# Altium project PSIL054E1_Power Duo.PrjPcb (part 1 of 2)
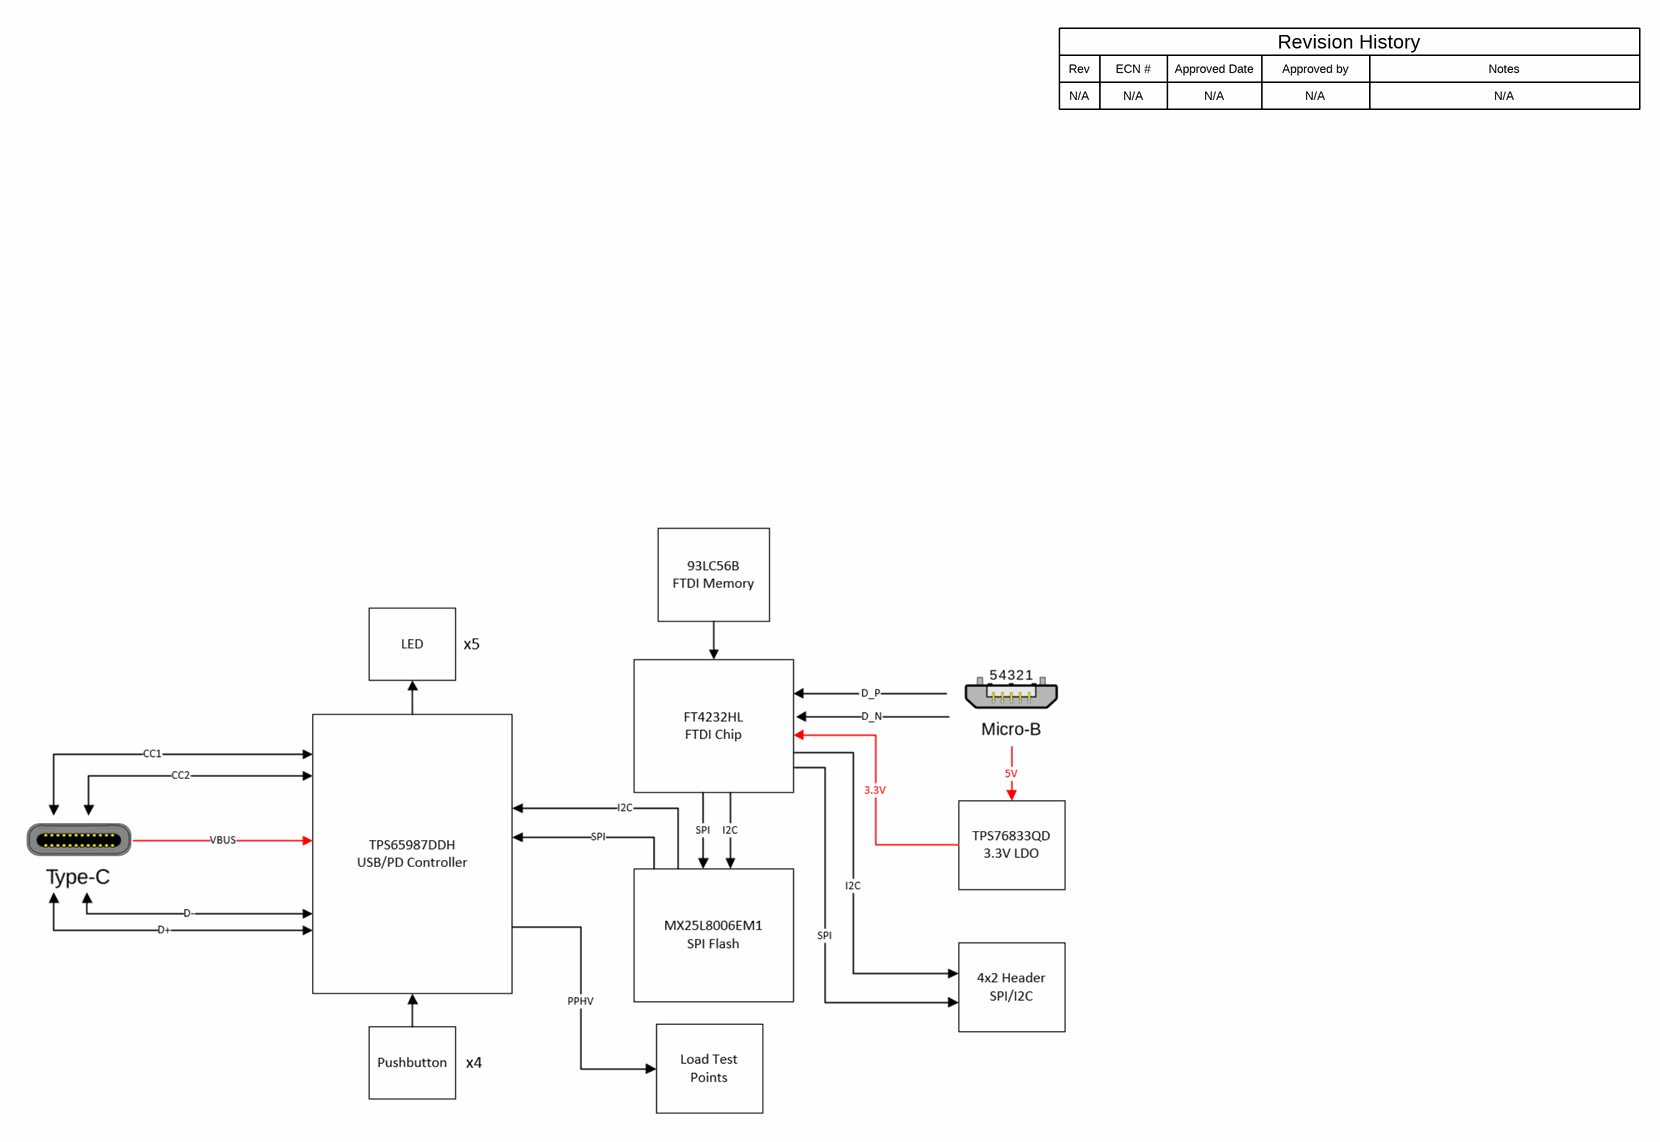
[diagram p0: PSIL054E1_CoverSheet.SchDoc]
CopyrightYear: 2018; PCB_Layout: Eric Beljaars/Adam McGaffin; PCB_Rev: E1; PRJ_Customer: Public Release; PRJ_Engineer: Eric Beljaars/Adam McGaffin; PRJ_Number: PSIL054; PRJ_Title: Power Duo; SCH_Rev: E1; TechSupport: http://www.ti.com/support; TID: TIDA-050014
9 sheets, 248 parts. Net scope: flat (ports and power ports of the same name join across sheets).
Board file: PSIL054E1_PCB.PcbDoc
Sheets:
  PSIL054E1_CoverSheet.SchDoc
  PSIL054E1_Variable DCDC.SchDoc
  PSIL054E1_Source PD Controller.SchDoc
  PSIL054E1_Bypass Power Path.SchDoc
  PSIL054E1_Source Type-C Connector.SchDoc
  PSIL054E1_Sink PD Controller.SchDoc
  PSIL054E1_FTDI.SchDoc
  PSIL054E1_Sink Buttons LEDs.SchDoc
  PSIL054E1_EVM_Hardware.SchDoc

## Sheet PSIL054E1_CoverSheet.SchDoc
size 431 x 279 mm; Date: Not shown in title block; ApprovedBy: Not shown in title block; CheckedBy: Not shown in title block; Author: Not shown in title block; CompanyName: Not shown in title block; Engineer: Not shown in title block; Organization: Not shown in title block; Address1: Not shown in title block; Address2: Not shown in title block; Address3: Not shown in title block; Address4: Not shown in title block; DocumentNumber: 1; Revision: Use project parameter SCH_Rev; SheetNumber: 1; SheetTotal: 9; PageSetup: Record=PageOptions¦CenterHorizontal=True¦CenterVertical=True¦PrintScale=1.00¦XCorrection=1.00¦YCorrection=1.00¦PrintKind=0¦BorderSize=5000000¦LeftOffset=0¦BottomOffset=0¦Orientation=2¦PaperLength=1000¦PaperWidth=1000¦Scale=100¦PaperSource=15¦PrintQuality=600¦MediaType=1¦DitherType=10¦PaperKind=Letter¦PrintScaleMode=1

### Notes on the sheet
- Rev
- N/A
- ECN #
- Approved Date
- Approved by
- Revision History
- Notes

## Sheet PSIL054E1_Variable DCDC.SchDoc
size 431 x 279 mm; Date: Not shown in title block; ApprovedBy: Not shown in title block; CheckedBy: Not shown in title block; Author: Not shown in title block; CompanyName: Not shown in title block; Engineer: Not shown in title block; Organization: Not shown in title block; Address1: Not shown in title block; Address2: Not shown in title block; Address3: Not shown in title block; Address4: Not shown in title block; DocumentNumber: 1; Revision: Use project parameter SCH_Rev; SheetNumber: 2; SheetTotal: 9; PageSetup: Record=PageOptions¦CenterHorizontal=True¦CenterVertical=True¦PrintScale=1.00¦XCorrection=1.00¦YCorrection=1.00¦PrintKind=0¦BorderSize=5000000¦LeftOffset=0¦BottomOffset=0¦Orientation=2¦PaperLength=1000¦PaperWidth=1000¦Scale=100¦PaperSource=15¦PrintQuality=600¦MediaType=1¦DitherType=10¦PaperKind=Letter¦PrintScaleMode=1
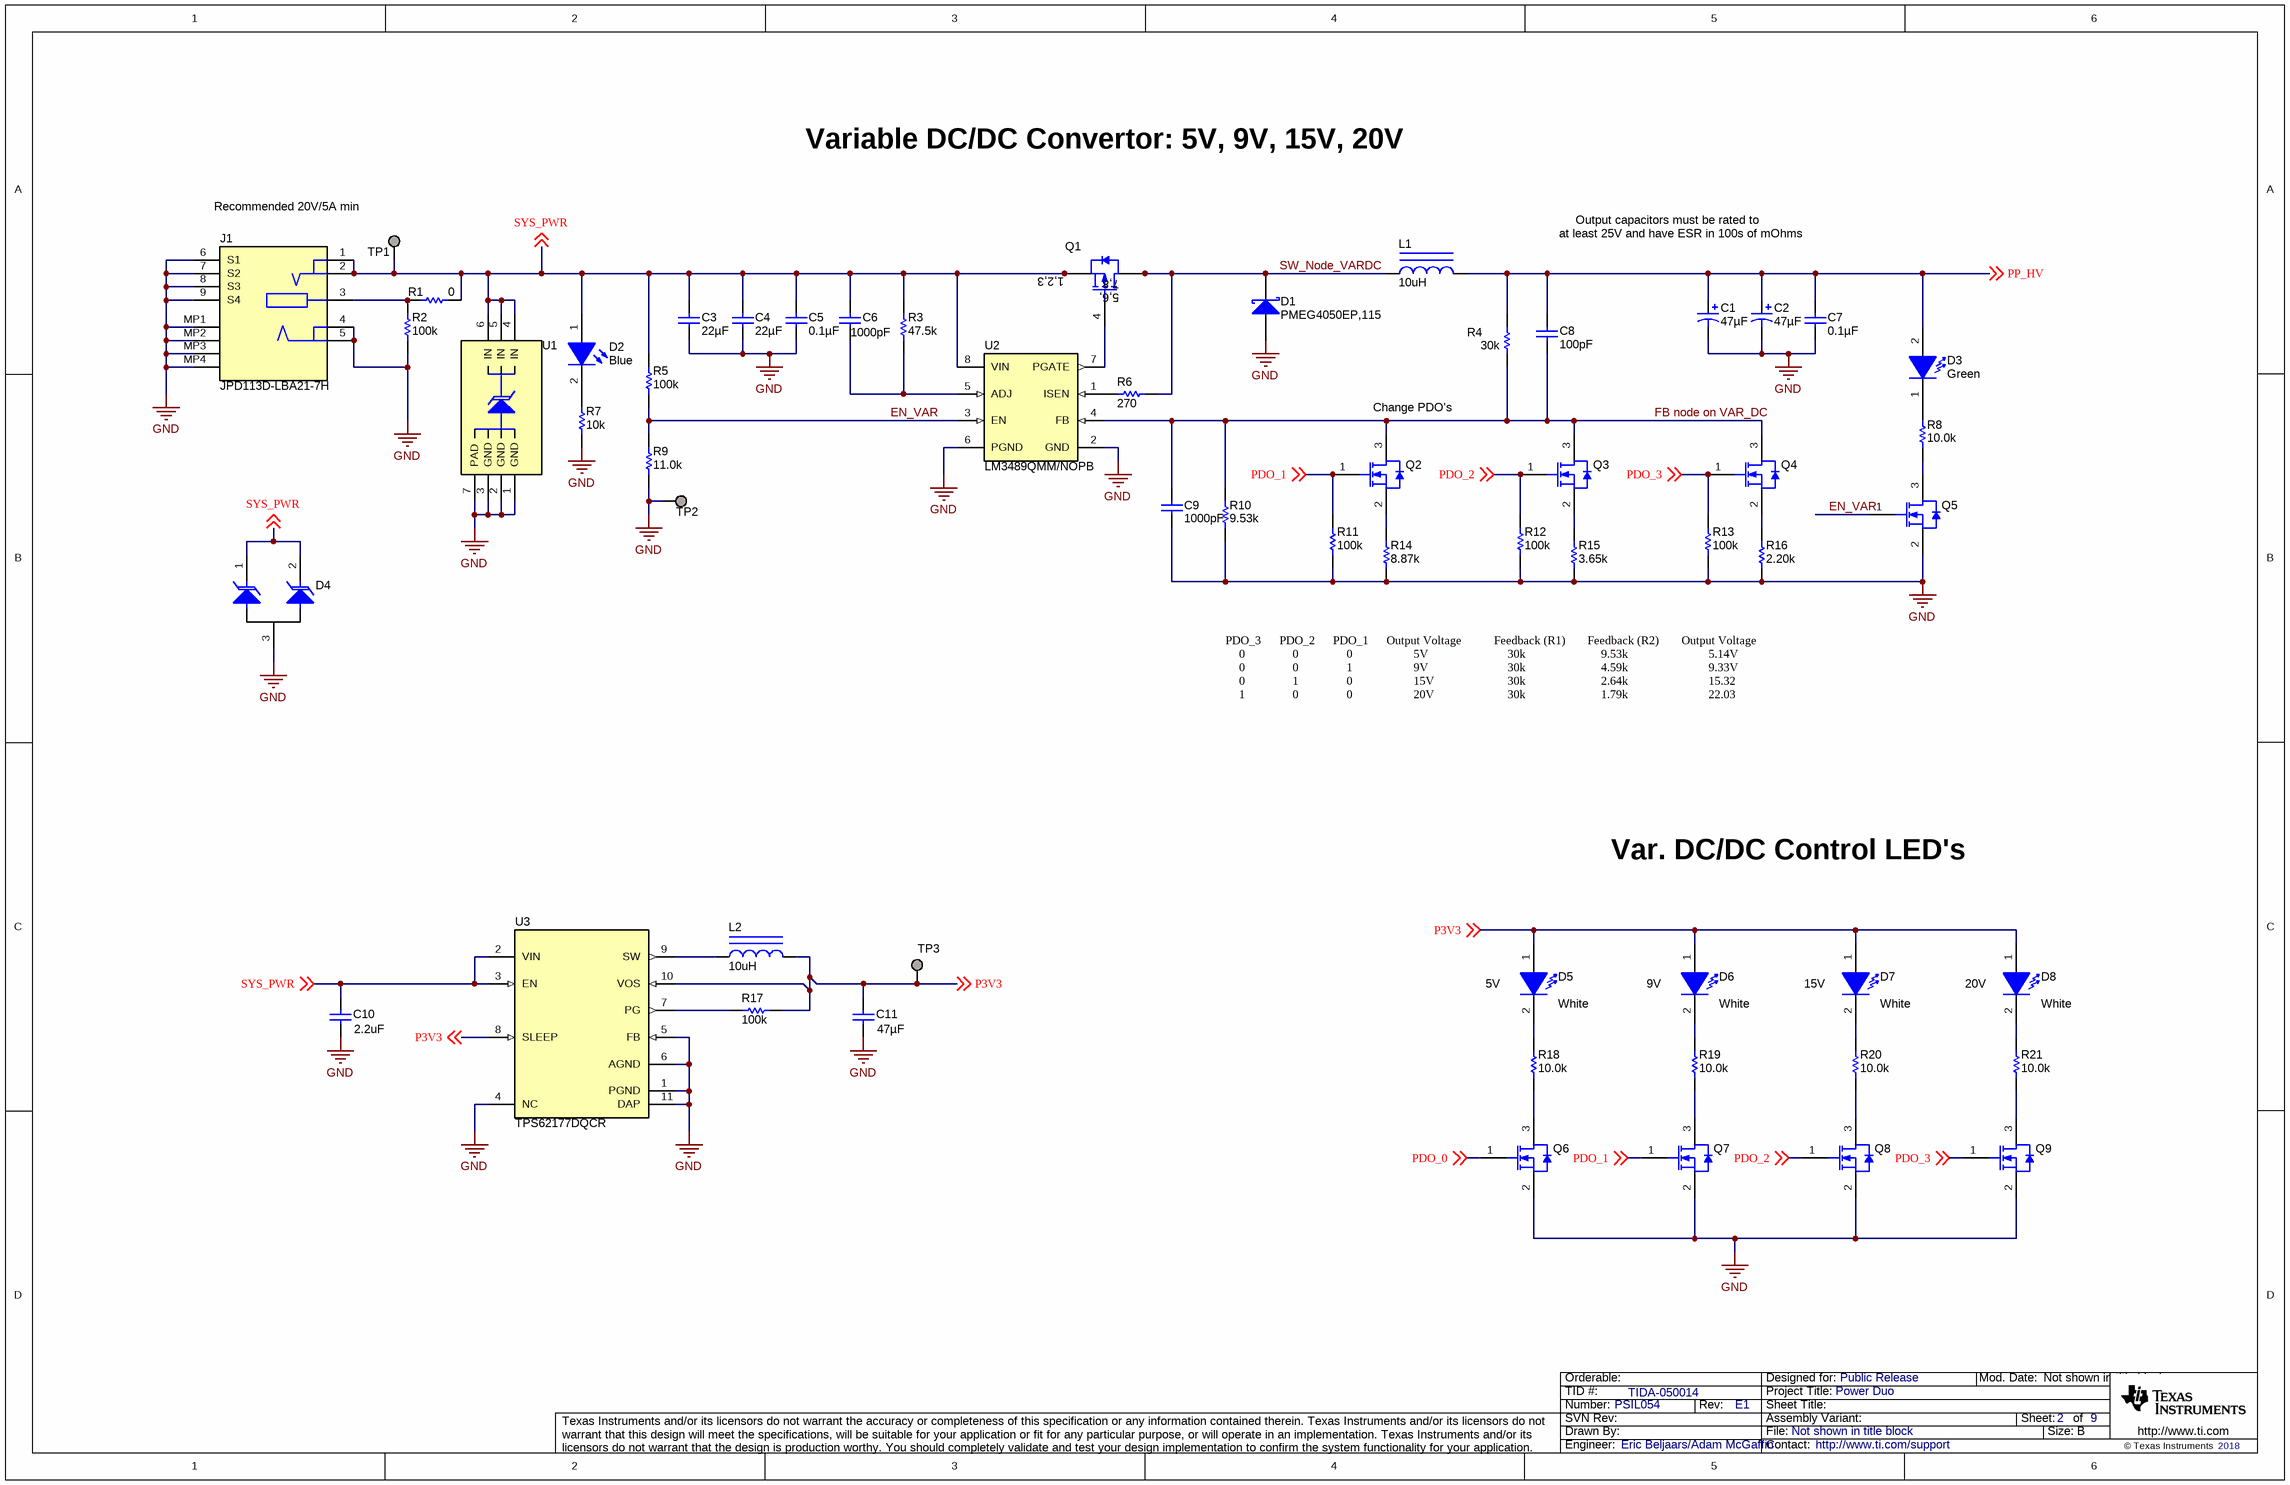
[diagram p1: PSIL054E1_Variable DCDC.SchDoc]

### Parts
C1  ValueDisplayed: 47µF  [7343-43]  (hidden comment: TAJE476M035RNJ)
C2  ValueDisplayed: 47µF  [7343-43]  (hidden comment: TAJE476M035RNJ)
C3  ValueDisplayed: 22µF  [0805_HV]  (hidden comment: C2012X5R1V226M125AC)
C4  ValueDisplayed: 22µF  [0805_HV]  (hidden comment: C2012X5R1V226M125AC)
C5  ValueDisplayed: 0.1µF  [0402]  (hidden comment: C1005X7R1H104K050BB)
C6  ValueDisplayed: 1000pF  [0402]  (hidden comment: C1005X7R1H102M050BE)
C7  ValueDisplayed: 0.1µF  [0402]  (hidden comment: GMK105BJ104KV-F)
C8  ValueDisplayed: 100pF  [0402]  (hidden comment: CC0402KRX7R9BB101)
C9  ValueDisplayed: 1000pF  [0402]  (hidden comment: C1005X7R1H102M050BE)
C10  ValueDisplayed: 2.2uF  [0402_065L]  (hidden comment: C1005X5R1V225K050BC)
C11  ValueDisplayed: 47µF  [0805_HV]  (hidden comment: GRM21BR60J476ME15L)
D1  PMEG4050EP,115  [SOD-128]
D2  value Blue  [LTST-C193_Blue]  (hidden comment: LTST-C193TBKT-5A)
D3  value Green  [WL-SMCW_GREEN]  (hidden comment: 150060GS75000)
D4  PESD24VS2UT,215  [SOT-23]  (value not drawn)
D5  value White  [LW QH8G_White]  (hidden comment: LW QH8G-Q2S2-3K5L-1)
D6  value White  [LW QH8G_White]  (hidden comment: LW QH8G-Q2S2-3K5L-1)
D7  value White  [LW QH8G_White]  (hidden comment: LW QH8G-Q2S2-3K5L-1)
D8  value White  [LW QH8G_White]  (hidden comment: LW QH8G-Q2S2-3K5L-1)
J1  JPD113D-LBA21-7H  [Foxconn_JPD113D-LBA21]
L1  ValueDisplayed: 10uH  [ASPI-0630LR]  (hidden comment: ASPI-0630LR-100M-T15)
L2  ValueDisplayed: 10uH  [WE-LHMI_4020]  (hidden comment: 74437324100)
Q1  AON7403  [TRANS_AOS_DFN3X3]  (value not drawn)
Q2  BSH105,215  [SOT-23]  (value not drawn)
Q3  BSH105,215  [SOT-23]  (value not drawn)
Q4  BSH105,215  [SOT-23]  (value not drawn)
Q5  NX3020NAKW,115  [SOT-323]  (value not drawn)
Q6  NX3020NAKW,115  [SOT-323]  (value not drawn)
Q7  NX3020NAKW,115  [SOT-323]  (value not drawn)
Q8  NX3020NAKW,115  [SOT-323]  (value not drawn)
Q9  NX3020NAKW,115  [SOT-323]  (value not drawn)
R1  ValueDisplayed: 0  [0805_HV]  (hidden comment: ERJ-6GEY0R00V)
R2  ValueDisplayed: 100k  [0402]  (hidden comment: CRCW0402100KFKED)
R3  ValueDisplayed: 47.5k  [0402]  (hidden comment: CRCW040247K5FKED)
R4  ValueDisplayed: 30k  [0402]  (hidden comment: CRCW040230K0JNED)
R5  ValueDisplayed: 100k  [0402]  (hidden comment: CRCW0402100KFKED)
R6  ValueDisplayed: 270  [0402]  (hidden comment: CRCW0402270RJNED)
R7  ValueDisplayed: 10k  [0603L]  (hidden comment: RC0603JR-0710KL)
R8  ValueDisplayed: 10.0k  [0402]  (hidden comment: ERJ-2RKF1002X)
R9  ValueDisplayed: 11.0k  [0402]  (hidden comment: CRCW040211K0FKED)
R10  ValueDisplayed: 9.53k  [0402]  (hidden comment: CRCW04029K53FKED)
R11  ValueDisplayed: 100k  [0402]  (hidden comment: CRCW0402100KFKED)
R12  ValueDisplayed: 100k  [0402]  (hidden comment: CRCW0402100KFKED)
R13  ValueDisplayed: 100k  [0402]  (hidden comment: CRCW0402100KFKED)
R14  ValueDisplayed: 8.87k  [0402]  (hidden comment: CRCW04028K87FKED)
R15  ValueDisplayed: 3.65k  [0402]  (hidden comment: CRCW04023K65FKED)
R16  ValueDisplayed: 2.20k  [0402]  (hidden comment: CRCW04022K20FKED)
R17  ValueDisplayed: 100k  [0402]  (hidden comment: CRCW0402100KFKED)
R18  ValueDisplayed: 10.0k  [0402L]  (hidden comment: ERJ-2RKF1002X)
R19  ValueDisplayed: 10.0k  [0402L]  (hidden comment: ERJ-2RKF1002X)
R20  ValueDisplayed: 10.0k  [0402L]  (hidden comment: ERJ-2RKF1002X)
R21  ValueDisplayed: 10.0k  [0402L]  (hidden comment: ERJ-2RKF1002X)
TP1  TESTPOINT  [Keystone_5019]  (value not drawn)
TP2  TESTPOINT  [Keystone_5019]  (value not drawn)
TP3  TESTPOINT  [Keystone_5019]  (value not drawn)
U1  TVS2200DRVR  [DRV0006A]  (value not drawn)
U2  LM3489QMM/NOPB  [MUA08A_N]
U3  TPS62177DQCR  [DQC0010A]

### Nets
GND: C1.2(-) C2.2(-) C3.2 C4.2 C5.2 C7.2 C9.2 C10.2 C11.2 D1.2(A) D4.3(A) J1.4(V-) J1.5(V-) J1.6(S1) J1.7(S2) J1.8(S3) J1.9(S4) J1.MP1 J1.MP2 J1.MP3 J1.MP4 Q5.2(S) Q6.2(S) Q7.2(S) Q8.2(S) Q9.2(S) R2.1 R7.1 R9.1 R10.1 R11.1 R12.1 R13.1 R14.1 R15.1 R16.1 TP2.1 U1.1(GND) U1.2(GND) U1.3(GND) U1.7(PAD) U2.2(GND) U2.6(PGND) U3.1(PGND) U3.4(NC) U3.5(FB) U3.6(AGND) U3.11(DAP)
EN_VAR: Q5.1(G) R5.1 R9.2 U2.3(EN)
FB node on VAR_DC: C8.2 C9.1 Q2.3(D) Q3.3(D) Q4.3(D) R4.1 R10.2 U2.4(FB)
P3V3: C11.1 D5.1(A) D6.1(A) D7.1(A) D8.1(A) L2.2 R17.2 TP3.1 U3.8(SLEEP) U3.10(VOS) ; off-sheet P3V3
PDO_0: Q6.1(G) ; off-sheet PDO_0
PDO_1: Q2.1(G) Q7.1(G) R11.2 ; off-sheet PDO_1
PDO_2: Q3.1(G) Q8.1(G) R12.2 ; off-sheet PDO_2
PDO_3: Q4.1(G) Q9.1(G) R13.2 ; off-sheet PDO_3
PP_HV: C1.1(+) C2.1(+) C7.1 C8.1 D3.2(A) L1.2 R4.2 ; off-sheet PP_HV
SW_Node_VARDC: D1.1(K) L1.1 Q1.5(D) Q1.6(D) Q1.7(D) Q1.8(D) R6.2
SYS_PWR: C3.1 C4.1 C5.1 C6.1 C10.1 D2.1(A) D4.1(C) D4.2(C) J1.1(V+) J1.2(V+) Q1.1(S) Q1.2(S) Q1.3(S) R1.2 R3.2 R5.2 TP1.1 U1.4(IN) U1.5(IN) U1.6(IN) U2.8(VIN) U3.2(VIN) U3.3(EN) ; off-sheet SYS_PWR
NetC6_2: C6.2 R3.1 U2.5(ADJ)
NetD2_2: D2.2(K) R7.2
NetD3_1: D3.1(K) R8.2
NetD5_2: D5.2(K) R18.2
NetD6_2: D6.2(K) R19.2
NetD7_2: D7.2(K) R20.2
NetD8_2: D8.2(K) R21.2
NetJ1_3: J1.3(ID) R1.1 R2.2
NetL2_1: L2.1 U3.9(SW)
NetQ1_4: Q1.4(G) U2.7(PGATE)
NetQ2_2: Q2.2(S) R14.2
NetQ3_2: Q3.2(S) R15.2
NetQ4_2: Q4.2(S) R16.2
NetQ5_3: Q5.3(D) R8.1
NetQ6_3: Q6.3(D) R18.1
NetQ7_3: Q7.3(D) R19.1
NetQ8_3: Q8.3(D) R20.1
NetQ9_3: Q9.3(D) R21.1
NetR6_1: R6.1 U2.1(ISEN)
NetR17_1: R17.1 U3.7(PG)

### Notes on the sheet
- Variable DC/DC Convertor: 5V, 9V, 15V, 20V
- Recommended 20V/5A min
- Output capacitors must be rated to
- at least 25V and have ESR in 100s of mOhms
- Change PDO's
- PDO_3
- 0
- 1
- PDO_2
- PDO_1
- Output Voltage
- 5V
- 9V
- 15V
- 20V
- Feedback (R1)
- 30k
- Feedback (R2)
- 9.53k
- 4.59k
- 2.64k
- 1.79k
- 5.14V
- 9.33V
- 15.32
- 22.03
- Var. DC/DC Control LED's
- (near D5) 5V
- (near D6) 9V
- (near D7) 15V
- (near D8) 20V

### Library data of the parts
C1 C2 = TAJE476M035RNJ: CAP, TA, 47 µF, 35 V, +/- 20%, 0.9 ohm, AEC-Q200 Grade 1, SMD; Manufacturer: AVX; Polarized: Y; CompType: Capacitor; Value: 47uF; U/M: EA; Cap_F: 0.000047; Tolerance_%: 20; Value1: 0.9 ohm; VDC_V: 35; Value2: 35V; ESR_ohm: 0.9; IRMS_A: 0.428; TaMin_C: -55; TaMax_C: 125; SizeAreaWB_mm2: 58.59; SizeArea_mm2: 31.39; SizeX_mm: 7.3; SizeY_mm: 4.3; AEC Category: Q200; AEC Grade: 1
C3 C4 = C2012X5R1V226M125AC: CAP, CERM, 22 µF, 35 V, +/- 20%, X5R, 0805; Manufacturer: TDK; Polarized: N; CompType: Capacitor; Value: 22uF; U/M: EA; Cap_F: 0.000022; Tolerance_%: 20; Value1: Unknown; VDC_V: 35; Value2: 35V; TaMin_C: -55; TaMax_C: 85; Cap_Case: 0805
C5 = C1005X7R1H104K050BB: CAP, CERM, 0.1 µF, 50 V, +/- 10%, X7R, 0402; Manufacturer: TDK; Polarized: N; CompType: Capacitor; Value: 0.1uF; U/M: EA; Cap_F: 0.0000001; Tolerance_%: 10; Value1: Unknown; VDC_V: 50; Value2: 50V; TaMin_C: -55; TaMax_C: 125; AEC Category: Q200
C6 C9 = C1005X7R1H102M050BE: CAP, CERM, 1000 pF, 50 V,+/- 20%, X7R, 0402; Manufacturer: TDK; Polarized: N; CompType: Capacitor; Value: 1000pF; U/M: EA; Cap_F: 0.000000001; Tolerance_%: 20; VDC_V: 50; Value2: 50V; TaMin_C: -55; TaMax_C: 125; SizeArea_mm2: 0.5; SizeAreaWB_mm2: 3; SizeX_mm: 1; SizeZ_mm: 0.6; AEC Category: Q200
C7 = GMK105BJ104KV-F: CAP, CERM, 0.1 µF, 35 V, +/- 10%, X5R, 0402; Manufacturer: Taiyo Yuden; Polarized: N; CompType: Capacitor; Value: 0.1uF; U/M: EA; Cap_F: 0.0000001; Tolerance_%: 10; Value1: Unknown; VDC_V: 35; Value2: 35V; TaMin_C: -55; TaMax_C: 85; AEC Category: Q200
C8 = CC0402KRX7R9BB101: CAP, CERM, 100 pF, 50 V,+/- 10%, X7R, 0402; Manufacturer: Yageo America; Polarized: N; CompType: Capacitor; Value: 100pF; U/M: EA; Cap_F: 0.0000000001; Tolerance_%: 10; VDC_V: 50; Value2: 50V; TaMin_C: -55; TaMax_C: 125; SizeArea_mm2: 0.5; SizeAreaWB_mm2: 3; SizeX_mm: 1; SizeZ_mm: 0.6; AEC Category: Q200; Green_Lifecycle: Active; Green_REACh: Passed
C10 = CMP-0006283-2: CAP, CERM, 2.2 uF, 35 V, +/- 10%, X5R, 0402; Manufacturer: TDK; TaMin_C: -55°C; ESR_ohm: 5.925m; Polarized: N; SizeAreaWB_mm2: 3; Value1: 0.005925 ohm; U/M: EA; Value: 2.2uF; TaMax_C: 85°C; SizeZ_mm: 0.65; SizeX_mm: 1; SizeY_mm: 0.5; Cap_Case: 0402_065; Value2: 35V; CompType: Capacitor; Cap_F: 2.2µF; IRMS_A: 2.05591A; AEC Category: Q200
C11 = GRM21BR60J476ME15L: CAP, CERM, 47 µF, 6.3 V, +/- 20%, X5R, 0805; Manufacturer: MuRata; Polarized: N; CompType: Capacitor; Value: 47uF; U/M: EA; Cap_F: 0.000047; Tolerance_%: 20; Value1: Unknown; VDC_V: 6.3; Value2: 6.3V; TaMin_C: -55; TaMax_C: 85; Cap_Case: 0805; SizeArea_mm2: 2.5; SizeAreaWB_mm2: 6.75; SizeX_mm: 2; SizeY_mm: 1.25; SizeZ_mm: 1.45; AEC Category: Q200
D1 = CMP-0077825-1: Diode, Schottky, 40 V, 5 A, AEC-Q101, SOD-128; Manufacturer: Nexperia; SizeAreaWB_mm2: 19.6; Vr_V: 40V; SizeArea_mm2: 11.5; AEC Qualified: Y; TJmax_C: 150°C; AEC Category: Q101; Value: 40V; SizeZ_mm: 1.1; Io_A: 5A; Vf_V: 4.9dV; SizeY_mm: 2.5; Value2: .49V; SizeX_mm: 4.6
D2 = CMP-0002938-2: LED, Blue, SMD; Manufacturer: Lite-On; Io_A: 5mA; Power_TotalModule: 76mW; Tjmax_C: 80°C; Value1: 0.076W; U/M: EA; Angle: 130; Ir_A: 10µA; Vf_V: 2.8V; Type: InGaN; LuminousIntensity_IV: 15
D3 = 150060GS75000: LED, Green, SMD; Manufacturer: Wurth Elektronik; Type: InGaN; Vf_V: 3.2; Value2: 3.2V; Io_A: 0.02; Tjmax_C: 85; Value1: W; Angle: 140; U/M: EA
D4 = CMP-0079048-1: Diode, TVS, Uni, 24 V, 70 Vc, SOT-23; Manufacturer: Nexperia; SizeAreaWB_mm2: 14; Vr_V: 24V; SizeArea_mm2: 7.5; AEC Qualified: N; AEC Category: Q101; Value: 24V; SizeZ_mm: 1.1; SizeY_mm: 3; SizeX_mm: 2.5
D5-D8 = LW QH8G-Q2S2-3K5L-1: LED, White, SMD; Manufacturer: OSRAM; Vf_V: 2.8; Value2: 2.8V; Io_A: 0.005; Vr_V: 5; Ir_A: 1e-008; Tjmax_C: 95; Value1: W; Angle: 120; U/M: EA
J1 = CMP-0081194-3: Connector, DC Power Jack, R/A, 3 Pos, Gold, TH; Manufacturer: Foxconn; Cert_UL: Y; Gender: Female; Current_A: 10A
L1 = CMP-0059579-1: Inductor, Wirewound, 10 uH, 4 A, 0.068 ohm, SMD; Manufacturer: Abracon Corporation; Isat: 5.5A @ 30% inductance drop; Irms: 4A @ 40C rise; Green_Lifecycle: Not Set; SizeAreaWB_mm2: 79.58; DCR_ohm: 0.068; Green_REACh: Incomplete; Value: 10uH; Imax_A: 4A; SizeZ_mm: 3; SizeX_mm: 7.2; SizeY_mm: 6.65; SizeArea_mm2: 47.88; Ind_H: 10µH; AEC Qualified: N; AEC Category: Q200
L2 = CMP-0064080-1: Inductor, Shielded Drum Core, Powdered Iron, 10 uH, 1.5 A, 0.215 ohm, SMD; Manufacturer: Wurth Elektronik; Isat: 2.4A @ 20% inductance drop; Irms: 1.5A @ 40C rise; Green_Lifecycle: Active; SizeAreaWB_mm2: 27.577; DCR_ohm: 2.15d; Green_REACh: Passed; Value: 10uH; Imax_A: 1.5A; SizeZ_mm: 2; SizeX_mm: 4.45; SizeY_mm: 4.06; SizeArea_mm2: 18.067; Ind_H: 10µH; AEC Category: Q200
Q1 = CMP-0000004-2: MOSFET, P-CH, -30 V, -11 A, FET, 3x0.8x3mm; Alternate Manufacturer: None; Manufacturer: AOS; SizeZ_mm: 0.55; ChType: P; Value2: 18 nC; VdsMax_V: -30V; SizeX_mm: 3; SizeAreaWB_mm2: 16; Vgs_V: -25V; QgTyp_nC: 18; Value: -30V; SizeArea_mm2: 9; AEC Category: Q101; IdsMax_A: -11A; U/M: EA
Q2-Q4 = BSH105,215: MOSFET, N-CH, 20 V, 1.05 A, SOT-23; Manufacturer: NXP Semiconductor; Alternate Manufacturer: None; U/M: EA; ChType: N; Value: 20V; VdsMax_V: 20; Value1: 0.2 ohm; Rdson45_ohm: 0.2; Value2: 3.9 nC; QgTyp_nC: 3.9; Vgs_V: 8; IdsMax_A: 1.05; AEC Category: Q101
Q5-Q9 = NX3020NAKW,115: MOSFET, N-CH, 30 V, 0.18 A, SOT-323; Manufacturer: NXP Semiconductor; Alternate Manufacturer: None; U/M: EA; ChType: N; Value: 30V; VdsMax_V: 30; Value1: 5.2 ohm; Rdson45_ohm: 5.2; Value2: 0.34 nC; QgTyp_nC: 0.34; Vgs_V: 20; IdsMax_A: 0.18; SizeAreaWB_mm2: 10.24; SizeArea_mm2: 4.84; SizeX_mm: 2.2; SizeZ_mm: 1.1; AEC Category: Q101
R1 = ERJ-6GEY0R00V: RES, 0, 5%, 0.125 W, 0805; Manufacturer: Panasonic; CompType: Resistor; Value: 0; Value_Code: 0000; Tolerance_%: 5; Power_W: 0.125; Value2: 0.125W; VDC_V: 150; TempCo: 600 ppm/C; SizeArea_mm2: 2.5; SizeX_mm: 2; SizeY_mm: 1.25; SizeZ_mm: 1.45; EIA_Code: E24; U/M: EA; AEC Category: Q200
R2 R5 R11-R13 = CRCW0402100KFKED: RES, 100 k, 1%, 0.063 W, 0402; Manufacturer: Vishay-Dale; CompType: Resistor; Value: 100k; Res_ohm: 100000; Tolerance_%: 1; Power_W: 0.063; Value2: 0.063W; VDC_V: 50; TempCo: 100 ppm/C; SizeArea_mm2: 0.5; SizeZ_mm: 0.6; EIA_Code: E96; U/M: EA; AEC Category: Q200; Green_Lifecycle: Active; Green_REACh: Passed
R3 = CRCW040247K5FKED: RES, 47.5 k, 1%, 0.063 W, 0402; Manufacturer: Vishay-Dale; CompType: Resistor; Value: 47.5k; Res_ohm: 47500; Value_Code: 47k5; Tolerance_%: 1; Power_W: 0.063; Value2: 0.063W; VDC_V: 50; TempCo: 100 ppm/C; SizeArea_mm2: 0.5; SizeZ_mm: 0.6; EIA_Code: E96; U/M: EA; AEC Category: Q200; Green_Lifecycle: Active; Green_REACh: Passed
R4 = CRCW040230K0JNED: RES, 30 k, 5%, 0.063 W, 0402; Manufacturer: Vishay-Dale; CompType: Resistor; Value: 30k; Res_ohm: 30000; Value_Code: 30k0; Tolerance_%: 5; Power_W: 0.063; Value2: 0.063W; VDC_V: 50; TempCo: 200 ppm/C; EIA_Code: E24; U/M: EA; AEC Category: Q200
R6 = CRCW0402270RJNED: RES, 270, 5%, 0.063 W, 0402; Manufacturer: Vishay-Dale; CompType: Resistor; Value: 270; Value_Code: 270R; Tolerance_%: 5; Power_W: 0.063; Value2: 0.063W; VDC_V: 50; TempCo: 200 ppm/C; EIA_Code: E24; U/M: EA; AEC Category: Q200
R7 = RC0603JR-0710KL: RES, 10 k, 5%, 0.1 W, 0603; Manufacturer: Yageo America; CompType: Resistor; Value: 10k; Res_ohm: 10000; Value_Code: 10k0; Tolerance_%: 5; Power_W: 0.1; Value2: 0.1W; VDC_V: 50; TempCo: 100 ppm/C; SizeArea_mm2: 1.28; SizeX_mm: 1.6; SizeY_mm: 0.8; SizeZ_mm: 1; EIA_Code: E24; U/M: EA; AEC Category: Q200; Green_Lifecycle: Active; Green_REACh: Passed
R8 R18-R21 = ERJ-2RKF1002X: RES, 10.0 k, 1%, 0.1 W, 0402; Manufacturer: Panasonic; CompType: Resistor; Value: 10.0k; Res_ohm: 10000; Value_Code: 10k0; Tolerance_%: 1; Power_W: 0.1; Value2: 0.1W; VDC_V: 50; TempCo: 100 ppm/C; SizeArea_mm2: 0.5; SizeZ_mm: 0.6; EIA_Code: E96; U/M: EA; AEC Category: Q200; Green_Lifecycle: Active; Green_REACh: Passed
R9 = CRCW040211K0FKED: RES, 11.0 k, 1%, 0.063 W, 0402; Manufacturer: Vishay-Dale; CompType: Resistor; Value: 11.0k; Res_ohm: 11000; Value_Code: 11k0; Tolerance_%: 1; Power_W: 0.063; Value2: 0.063W; VDC_V: 50; TempCo: 100 ppm/C; SizeArea_mm2: 0.5; SizeZ_mm: 0.6; EIA_Code: E96; U/M: EA; AEC Category: Q200
R10 = CRCW04029K53FKED: RES, 9.53 k, 1%, 0.063 W, 0402; Manufacturer: Vishay-Dale; CompType: Resistor; Value: 9.53k; Res_ohm: 9530; Value_Code: 9k53; Tolerance_%: 1; Power_W: 0.063; Value2: 0.063W; VDC_V: 50; TempCo: 100 ppm/C; EIA_Code: E96; U/M: EA; AEC Category: Q200
R14 = CRCW04028K87FKED: RES, 8.87 k, 1%, 0.063 W, 0402; Manufacturer: Vishay-Dale; CompType: Resistor; Value: 8.87k; Res_ohm: 8870; Value_Code: 8k87; Tolerance_%: 1; Power_W: 0.063; Value2: 0.063W; VDC_V: 50; TempCo: 100 ppm/C; EIA_Code: E96; U/M: EA; AEC Category: Q200
R15 = CRCW04023K65FKED: RES, 3.65 k, 1%, 0.063 W, 0402; Manufacturer: Vishay-Dale; CompType: Resistor; Value: 3.65k; Res_ohm: 3650; Value_Code: 3k65; Tolerance_%: 1; Power_W: 0.063; Value2: 0.063W; VDC_V: 50; TempCo: 100 ppm/C; SizeArea_mm2: 0.5; SizeZ_mm: 0.6; EIA_Code: E96; U/M: EA; AEC Category: Q200
R16 = CRCW04022K20FKED: RES, 2.20 k, 1%, 0.063 W, 0402; Manufacturer: Vishay-Dale; CompType: Resistor; Value: 2.20k; Res_ohm: 2200; Value_Code: 2k20; Tolerance_%: 1; Power_W: 0.063; Value2: 0.063W; TempCo: 100 ppm/C; U/M: EA; AEC Category: Q200
R17 = CMP-0025950-3: RES, 100 k, 1%, 0.063 W, AEC-Q200 Grade 0, 0402; Manufacturer: Vishay-Dale; Power_W: 63mW; TempCo: 100 ppm/C; Value: 100k; EIA_Code: E96; SizeX_mm: 1; SizeY_mm: 0.5; SizeZ_mm: 0.6; Value2: 0.063W; AEC Qualified: Y; VDC_V: 50V; AEC Category: Q200; AEC Grade: 0
TP1-TP3 = 5019: Test Point, Miniature, SMT; Manufacturer: Keystone; CompType: Test Point Loop; U/M: EA
U1 = CMP-0077834-1: 22-V Precision Surge Protection Clamp, DRV0006A (WSON-6); Alternate Manufacturer: Texas Instruments; SizeAreaWB_mm2: 9.0; SizeZ_mm: 0.8; SizeX_mm: 2.0; SizeArea_mm2: 4.0; CompType: IC; AEC Qualified: N; AEC Category: Q200
U2 = LM3489QMM/NOPB: Hysteretic PFET Buck Controller with Enable Pin, 8-pin MSOP, Pb-Free; Manufacturer: Texas Instruments; PackageTopMarking: ZXTT*STEB; PowerWise: N; CompType: Switcher
U3 = CMP-0067107-3: 28V, 0.5A Step-Down Converter with SNOOZE Mode, DQC0010A (WSON-10); Alternate PartNumber: TPS62177DQCT; Manufacturer: Texas Instruments; SizeZ_mm: 0.8; SizeX_mm: 2.0; SizeY_mm: 3.0; SizeArea_mm2: 6.0; CompType: IC; SizeAreaWB_mm2: 12.0

## Sheet PSIL054E1_Source PD Controller.SchDoc
size 431 x 279 mm; Date: Not shown in title block; ApprovedBy: Not shown in title block; CheckedBy: Not shown in title block; Author: Not shown in title block; CompanyName: Not shown in title block; Engineer: Not shown in title block; Organization: Not shown in title block; Address1: Not shown in title block; Address2: Not shown in title block; Address3: Not shown in title block; Address4: Not shown in title block; DocumentNumber: 1; Revision: Use project parameter SCH_Rev; SheetNumber: 3; SheetTotal: 9; PageSetup: Record=PageOptions¦CenterHorizontal=True¦CenterVertical=True¦PrintScale=1.00¦XCorrection=1.00¦YCorrection=1.00¦PrintKind=0¦BorderSize=5000000¦LeftOffset=0¦BottomOffset=0¦Orientation=2¦PaperLength=1000¦PaperWidth=1000¦Scale=100¦PaperSource=15¦PrintQuality=600¦MediaType=1¦DitherType=10¦PaperKind=Letter¦PrintScaleMode=1
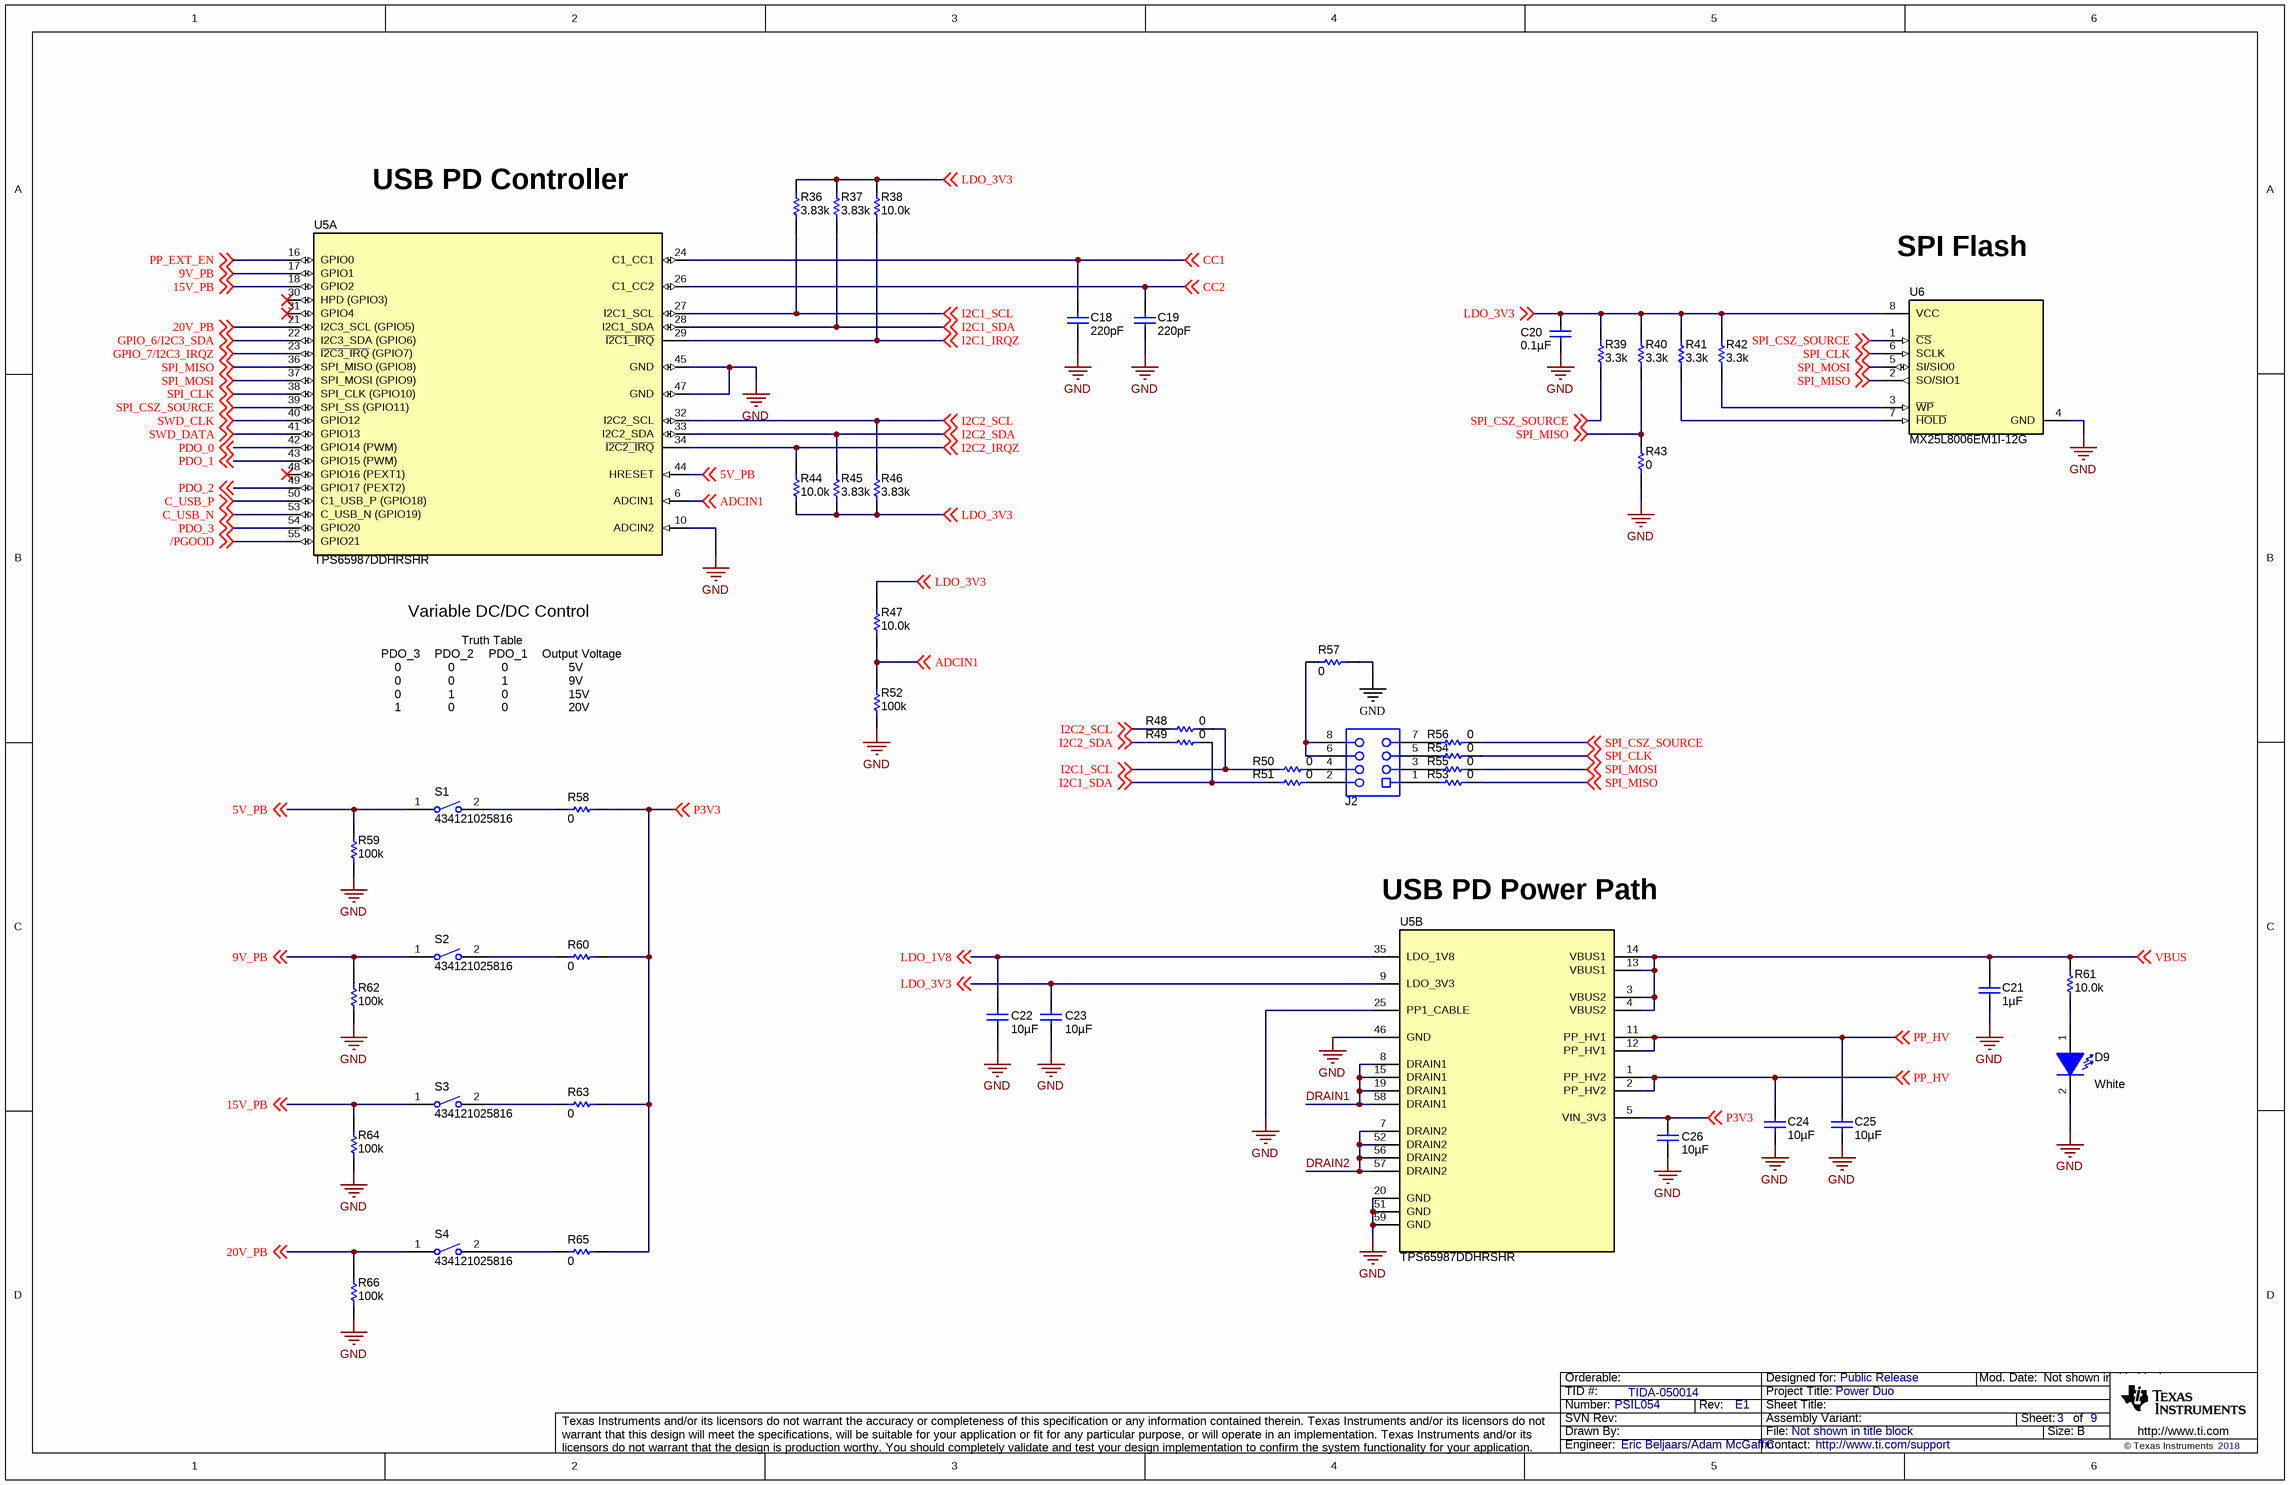
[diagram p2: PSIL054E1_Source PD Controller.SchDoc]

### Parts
C18  ValueDisplayed: 220pF  [0201]  (hidden comment: GRM033R71E221KA01D)
C19  ValueDisplayed: 220pF  [0201]  (hidden comment: GRM033R71E221KA01D)
C20  ValueDisplayed: 0.1µF  [0402]  (hidden comment: 885012205037)
C21  ValueDisplayed: 1µF  [0603]  (hidden comment: UMK107AB7105KA-T)
C22  ValueDisplayed: 10µF  [0402S]  (hidden comment: CL05A106MP5NUNC)
C23  ValueDisplayed: 10µF  [0402S]  (hidden comment: CL05A106MP5NUNC)
C24  ValueDisplayed: 10µF  [0603S]  (hidden comment: GRM188R61E106MA73D)
C25  ValueDisplayed: 10µF  [0603S]  (hidden comment: GRM188R61E106MA73D)
C26  ValueDisplayed: 10µF  [0402S]  (hidden comment: CL05A106MP5NUNC)
D9  value White  [LW QH8G_White]  (hidden comment: LW QH8G-Q2S2-3K5L-1)
J2  SSQ-104-03-G-D  [Samtec_SSQ-104-03-x-D]  (value not drawn)
R36  ValueDisplayed: 3.83k  [0402]  (hidden comment: CRCW04023K83FKED)
R37  ValueDisplayed: 3.83k  [0402]  (hidden comment: CRCW04023K83FKED)
R38  ValueDisplayed: 10.0k  [0402]  (hidden comment: ERJ-2RKF1002X)
R39  ValueDisplayed: 3.3k  [0402]  (hidden comment: CRCW04023K30JNED)
R40  ValueDisplayed: 3.3k  [0402]  (hidden comment: CRCW04023K30JNED)
R41  ValueDisplayed: 3.3k  [0402]  (hidden comment: CRCW04023K30JNED)
R42  ValueDisplayed: 3.3k  [0402]  (hidden comment: CRCW04023K30JNED)
R43  ValueDisplayed: 0  [0402L]  (hidden comment: RC0402JR-070RL)
R44  ValueDisplayed: 10.0k  [0402]  (hidden comment: ERJ-2RKF1002X)
R45  ValueDisplayed: 3.83k  [0402]  (hidden comment: CRCW04023K83FKED)
R46  ValueDisplayed: 3.83k  [0402]  (hidden comment: CRCW04023K83FKED)
R47  ValueDisplayed: 10.0k  [0201]  (hidden comment: CRCW020110K0FKED)
R48  ValueDisplayed: 0  [0201]  (hidden comment: CRCW02010000Z0ED)
R49  ValueDisplayed: 0  [0201]  (hidden comment: CRCW02010000Z0ED)
R50  ValueDisplayed: 0  [0201]  (hidden comment: CRCW02010000Z0ED)
R51  ValueDisplayed: 0  [0201]  (hidden comment: CRCW02010000Z0ED)
R52  ValueDisplayed: 100k  [0201]  (hidden comment: CRCW0201100KFKED)
R53  ValueDisplayed: 0  [0201]  (hidden comment: CRCW02010000Z0ED)
R54  ValueDisplayed: 0  [0201]  (hidden comment: CRCW02010000Z0ED)
R55  ValueDisplayed: 0  [0201]  (hidden comment: CRCW02010000Z0ED)
R56  ValueDisplayed: 0  [0201]  (hidden comment: CRCW02010000Z0ED)
R57  ValueDisplayed: 0  [0201]  (hidden comment: CRCW02010000Z0ED)
R58  ValueDisplayed: 0  [0402]  (hidden comment: CRCW04020000Z0EDHP)
R59  ValueDisplayed: 100k  [0402]  (hidden comment: CRCW0402100KDHEDP)
R60  ValueDisplayed: 0  [0402]  (hidden comment: CRCW04020000Z0EDHP)
R61  ValueDisplayed: 10.0k  [0402L]  (hidden comment: ERJ-2RKF1002X)
R62  ValueDisplayed: 100k  [0402]  (hidden comment: CRCW0402100KDHEDP)
R63  ValueDisplayed: 0  [0402]  (hidden comment: CRCW04020000Z0EDHP)
R64  ValueDisplayed: 100k  [0402]  (hidden comment: CRCW0402100KDHEDP)
R65  ValueDisplayed: 0  [0402]  (hidden comment: CRCW04020000Z0EDHP)
R66  ValueDisplayed: 100k  [0402]  (hidden comment: CRCW0402100KDHEDP)
S1  434121025816  [SW_434121025816]
S2  434121025816  [SW_434121025816]
S3  434121025816  [SW_434121025816]
S4  434121025816  [SW_434121025816]
U5  TPS65987DDHRSHR  [RSH0056E_NSMD]  (parts A,B of 2)
U6  MX25L8006EM1I-12G  [SOP-8_150MIL]

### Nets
GND: C18.2 C19.2 C20.2 C21.2 C22.2 C23.2 C24.2 C25.2 C26.2 D9.2(K) R43.1 R52.1 R57.1 R59.1 R62.1 R64.1 R66.1 U5.10(ADCIN2) U5.20(GND) U5.25(PP1_CABLE) U5.45(GND) U5.46(GND) U5.47(GND) U5.51(GND) U5.59(GND) U6.4(GND)
5V_PB: R59.2 S1.1 U5.44(HRESET) ; off-sheet 5V_PB
9V_PB: R62.2 S2.1 U5.17(GPIO1) ; off-sheet 9V_PB
15V_PB: R64.2 S3.1 U5.18(GPIO2) ; off-sheet 15V_PB
20V_PB: R66.2 S4.1 U5.21(I2C3_SCL_(GPIO5)) ; off-sheet 20V_PB
/PGOOD: U5.55(GPIO21) ; off-sheet /PGOOD
ADCIN1: R47.1 R52.2 U5.6(ADCIN1) ; off-sheet ADCIN1
C_USB_N: U5.53(C_USB_N_(GPIO19)) ; off-sheet C_USB_N
C_USB_P: U5.50(C1_USB_P_(GPIO18)) ; off-sheet C_USB_P
CC1: C18.1 U5.24(C1_CC1) ; off-sheet CC1
CC2: C19.1 U5.26(C1_CC2) ; off-sheet CC2
DRAIN1: U5.8(DRAIN1) U5.15(DRAIN1) U5.19(DRAIN1) U5.58(DRAIN1)
DRAIN2: U5.7(DRAIN2) U5.52(DRAIN2) U5.56(DRAIN2) U5.57(DRAIN2)
GPIO_6/I2C3_SDA: U5.22(I2C3_SDA_(GPIO6)) ; off-sheet GPIO_6/I2C3_SDA
GPIO_7/I2C3_IRQZ: U5.23(~{I2C3_IRQ}_(GPIO7)) ; off-sheet GPIO_7/I2C3_IRQZ
I2C1_IRQZ: R38.1 U5.29(~{I2C1_IRQ}) ; off-sheet I2C1_IRQZ
I2C1_SCL: R36.1 R48.2 R50.1 U5.27(I2C1_SCL) ; off-sheet I2C1_SCL
I2C1_SDA: R37.1 R49.2 R51.1 U5.28(I2C1_SDA) ; off-sheet I2C1_SDA
I2C2_IRQZ: R44.2 U5.34(~{I2C2_IRQ}) ; off-sheet I2C2_IRQZ
I2C2_SCL: R46.2 R48.1 U5.32(I2C2_SCL) ; off-sheet I2C2_SCL
I2C2_SDA: R45.2 R49.1 U5.33(I2C2_SDA) ; off-sheet I2C2_SDA
LDO_1V8: C22.1 U5.35(LDO_1V8) ; off-sheet LDO_1V8
LDO_3V3: C20.1 C23.1 R36.2 R37.2 R38.2 R39.1 R40.1 R41.2 R42.1 R44.1 R45.1 R46.1 R47.2 U5.9(LDO_3V3) U6.8(VCC) ; off-sheet LDO_3V3
P3V3: C26.1 R58.2 R60.2 R63.2 R65.2 U5.5(VIN_3V3) ; off-sheet P3V3
PDO_0: U5.42(GPIO14_(PWM)) ; off-sheet PDO_0
PDO_1: U5.43(GPIO15_(PWM)) ; off-sheet PDO_1
PDO_2: U5.49(GPIO17_(PEXT2)) ; off-sheet PDO_2
PDO_3: U5.54(GPIO20) ; off-sheet PDO_3
PP_EXT_EN: U5.16(GPIO0) ; off-sheet PP_EXT_EN
PP_HV: C24.1 C25.1 U5.1(PP_HV2) U5.2(PP_HV2) U5.11(PP_HV1) U5.12(PP_HV1) ; off-sheet PP_HV
SPI_CLK: R54.1 U5.38(SPI_CLK_(GPIO10)) U6.6(SCLK) ; off-sheet SPI_CLK
SPI_CSZ_SOURCE: R39.2 R56.1 U5.39(SPI_SS_(GPIO11)) U6.1(~{CS}) ; off-sheet SPI_CSZ_SOURCE
SPI_MISO: R40.2 R43.2 R53.1 U5.36(SPI_MISO_(GPIO8)) U6.2(SO/SIO1) ; off-sheet SPI_MISO
SPI_MOSI: R55.2 U5.37(SPI_MOSI_(GPIO9)) U6.5(SI/SIO0) ; off-sheet SPI_MOSI
SWD_CLK: U5.40(GPIO12) ; off-sheet SWD_CLK
SWD_DATA: U5.41(GPIO13) ; off-sheet SWD_DATA
VBUS: C21.1 R61.2 U5.3(VBUS2) U5.4(VBUS2) U5.13(VBUS1) U5.14(VBUS1) ; off-sheet VBUS
NetD9_1: D9.1(A) R61.1
NetJ2_1: J2.1 R53.2
NetJ2_2: J2.2 R51.2
NetJ2_3: J2.3 R55.1
NetJ2_4: J2.4 R50.2
NetJ2_5: J2.5 R54.2
NetJ2_6: J2.6 J2.8 R57.2
NetJ2_7: J2.7 R56.2
NetR41_1: R41.1 U6.7(~{HOLD})
NetR42_2: R42.2 U6.3(~{WP})
NetR58_1: R58.1 S1.2
NetR60_1: R60.1 S2.2
NetR63_1: R63.1 S3.2
NetR65_1: R65.1 S4.2

Not connected (* = marked no-connect by the designer): U5 30(HPD_(GPIO3))* 31(GPIO4)* 48(GPIO16_(PEXT1))*

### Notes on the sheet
- USB PD Controller
- (near U6) SPI Flash
- Variable DC/DC Control
- PDO_3
- 0
- PDO_2
- 1
- Truth Table
- PDO_1
- Output Voltage
- 5V
- 9V
- 15V
- 20V
- (near U5) USB PD Power Path

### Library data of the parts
C18 C19 = GRM033R71E221KA01D: CAP, CERM, 220 pF, 25 V, +/- 10%, X7R, 0201; Manufacturer: MuRata; Polarized: N; CompType: Capacitor; Value: 220pF; U/M: EA; Cap_F: 0.00000000022; Tolerance_%: 10; Value1: Unknown; VDC_V: 25; Value2: 25V; TaMin_C: -55; TaMax_C: 125; SizeArea_mm2: 0.18; SizeAreaWB_mm2: 2.08; SizeX_mm: 0.6; SizeY_mm: 0.3; SizeZ_mm: 0.26; AEC Category: Q200
C20 = 885012205037: CAP, CERM, 0.1 µF, 16 V,+/- 10%, X7R, 0402; Manufacturer: Wurth Elektronik; Polarized: N; CompType: Capacitor; Value: 0.1uF; U/M: EA; Cap_F: 0.0000001; Tolerance_%: 10; VDC_V: 16; Value2: 16V; TaMin_C: -55; TaMax_C: 125; SizeArea_mm2: 0.5; SizeAreaWB_mm2: 3; SizeX_mm: 1; SizeZ_mm: 0.6; AEC Category: Q200; Green_Lifecycle: Active; Green_REACh: Passed
C21 = UMK107AB7105KA-T: CAP, CERM, 1 µF, 50 V,+/- 10%, X7R, 0603; Manufacturer: Taiyo Yuden; Polarized: N; CompType: Capacitor; Value: 1uF; U/M: EA; Cap_F: 0.000001; Tolerance_%: 10; VDC_V: 50; Value2: 50V; TaMin_C: -55; TaMax_C: 125; SizeArea_mm2: 1.28; SizeAreaWB_mm2: 4.68; SizeX_mm: 1.6; SizeY_mm: 0.8; SizeZ_mm: 1; AEC Category: Q200; Green_Lifecycle: Active; Green_REACh: Passed
C22 C23 C26 = CL05A106MP5NUNC: CAP, CERM, 10 µF, 10 V, +/- 20%, X5R, 0402; Manufacturer: Samsung Electro-Mechanics; Polarized: N; CompType: Capacitor; Value: 10uF; U/M: EA; Cap_F: 0.00001; Tolerance_%: 20; Value1: Unknown; VDC_V: 10; Value2: 10V; TaMin_C: -55; TaMax_C: 85; Cap_Case: 0402; SizeArea_mm2: 0.5; SizeAreaWB_mm2: 3; SizeX_mm: 1; SizeZ_mm: 0.6; AEC Category: Q200
C24 C25 = GRM188R61E106MA73D: CAP, CERM, 10 µF, 25 V, +/- 20%, X5R, 0603; Manufacturer: MuRata; Polarized: N; CompType: Capacitor; Value: 10uF; U/M: EA; Cap_F: 0.00001; Tolerance_%: 20; Value1: Unknown; VDC_V: 25; Value2: 25V; TaMin_C: -55; TaMax_C: 85; Cap_Case: 0603; SizeArea_mm2: 1.28; SizeAreaWB_mm2: 4.68; SizeX_mm: 1.6; SizeY_mm: 0.8; SizeZ_mm: 1; AEC Category: Q200
D9 = LW QH8G-Q2S2-3K5L-1: as D5 on sheet PSIL054E1_Variable DCDC
J2 = SSQ-104-03-G-D: Receptacle, 2.54mm, 4x2, Gold, TH; Manufacturer: Samtec; SymbolCreator: a0412235; CompType: Socket Strip; Pitch_mm: 2.54; Gender: Female; Row_Count: 2; Current_A: 6.3; Cert_CSA: Y
R36 R37 R46 = CRCW04023K83FKED: RES, 3.83 k, 1%, 0.063 W, 0402; Manufacturer: Vishay-Dale; CompType: Resistor; Value: 3.83k; Res_ohm: 3830; Value_Code: 3k83; Tolerance_%: 1; Power_W: 0.063; Value2: 0.063W; VDC_V: 50; TempCo: 100 ppm/C; SizeArea_mm2: 0.5; SizeZ_mm: 0.6; EIA_Code: E96; U/M: EA; AEC Category: Q200; Green_Lifecycle: Active; Green_REACh: Passed
R38 R44 R61 = ERJ-2RKF1002X: as R8 on sheet PSIL054E1_Variable DCDC
R39-R42 = CRCW04023K30JNED: RES, 3.3 k, 5%, 0.063 W, 0402; Manufacturer: Vishay-Dale; CompType: Resistor; Value: 3.3k; Res_ohm: 3300; Value_Code: 3k30; Tolerance_%: 5; Power_W: 0.063; Value2: 0.063W; VDC_V: 50; TempCo: 200 ppm/C; EIA_Code: E24; U/M: EA
R43 = RC0402JR-070RL: RES, 0, 5%, 0.063 W, 0402; Manufacturer: Yageo America; CompType: Resistor; Value: 0; Value_Code: 0000; Tolerance_%: 5; Power_W: 0.063; Value2: 0.063W; VDC_V: 50; TempCo: 200 ppm/C; SizeArea_mm2: 0.5; SizeX_mm: 1; SizeZ_mm: 0.6; EIA_Code: E24; U/M: EA; AEC Category: Q200; Green_Lifecycle: Active; Green_REACh: Passed
R45 = CMP-0026339-2: RES, 3.83 k, 1%, 0.063 W, AEC-Q200 Grade 0, 0402; Manufacturer: Vishay-Dale; Power_W: 63mW; TempCo: 100 ppm/C; Value_Code: 3k83; Value: 3.83k; EIA_Code: E96; SizeX_mm: 1; SizeY_mm: 0.5; SizeZ_mm: 0.6; Value2: 0.063W; CompType: Resistor; AEC Qualified: Y; VDC_V: 50V; AEC Category: Q200; AEC Grade: 0
R47 = CMP-0027262-3: RES, 10.0 k, 1%, 0.05 W, 0201; Manufacturer: Vishay-Dale; Power_W: 50mW; TempCo: 100 ppm/C; Value_Code: 10k0; Value: 10.0k; EIA_Code: E96; Res_ohm: 10k; SizeX_mm: 0.6; SizeY_mm: 0.3; SizeZ_mm: 0.26; Value2: 0.05W; SizeArea_mm2: 0.18; AEC Qualified: N; VDC_V: 30V; AEC Category: Q200
R48-R51 R53-R57 = CMP-0027008-4: RES, 0, 5%, 0.05 W, 0201; Manufacturer: Vishay-Dale; Power_W: 50mW; TempCo: ppm/C; Value_Code: 0000; Value: 0; EIA_Code: E24; SizeX_mm: 0.6; SizeY_mm: 0.3; SizeZ_mm: 0.26; Value2: 0.05W; SizeArea_mm2: 0.18; CompType: Resistor; AEC Qualified: N; AEC Category: Q200
R52 = CMP-0027261-3: RES, 100 k, 1%, 0.05 W, 0201; Manufacturer: Vishay-Dale; Power_W: 50mW; TempCo: 100 ppm/C; Value: 100k; EIA_Code: E96; SizeX_mm: 0.6; SizeY_mm: 0.3; SizeZ_mm: 0.26; Value2: 0.05W; SizeArea_mm2: 0.18; AEC Qualified: N; VDC_V: 30V; AEC Category: Q200
R58 R60 R63 R65 = CMP-0081856-1: RES, 0, 0%, 0.2 W, AEC-Q200 Grade 0, 0402; Manufacturer: Vishay-Dale; SizeAreaWB_mm2: 3; SizeArea_mm2: 0.5; AEC Qualified: Y; AEC Category: Q200; Value: 0; SizeZ_mm: 0.6; Power_W: 200mW; VDC_V: 50V; Value2: 0.2W; SizeX_mm: 1
R59 R62 R64 R66 = CMP-0026768-2: RES, 100 k, 0.5%, 0.063 W, AEC-Q200 Grade 0, 0402; Manufacturer: Vishay-Dale; Power_W: 63mW; TempCo: 50 ppm/C; Value: 100k; EIA_Code: E192; SizeX_mm: 1; SizeY_mm: 0.5; SizeZ_mm: 0.6; Value2: 0.063W; AEC Qualified: Y; VDC_V: 50V; AEC Category: Q200; AEC Grade: 0
S1-S4 = CMP-0002196-2: Switch, Tactile, SPST, 12 V, SMD; Manufacturer: Wurth Elektronik; CurrentRating_mA: 50A; PositionCount: 1; VDC_V: 12V; SwitchFunction: Off-On
U5 = CMP-0081032-2: USB Type-C and USB PD Controller with Integrated Power Switches, RSH0056E (VQFN-56); Alternate PartNumber: TPS65987DDHRSHT; Alternate Manufacturer: Texas Instruments; SizeAreaWB_mm2: 81; SizeZ_mm: 1; SizeX_mm: 7; SizeArea_mm2: 49; CompType: IC; AEC Qualified: N; AEC Category: Q200
U6 = CMP-0078948-1: 8Mb, 86MHz, NOR Flash, SOP-8; Manufacturer: Macronix International Co., LTD

## Sheet PSIL054E1_Bypass Power Path.SchDoc
size 431 x 279 mm; Date: Not shown in title block; ApprovedBy: Not shown in title block; CheckedBy: Not shown in title block; Author: Not shown in title block; CompanyName: Not shown in title block; Engineer: Not shown in title block; Organization: Not shown in title block; Address1: Not shown in title block; Address2: Not shown in title block; Address3: Not shown in title block; Address4: Not shown in title block; DocumentNumber: 1; Revision: Use project parameter SCH_Rev; SheetNumber: 4; SheetTotal: 9; PageSetup: Record=PageOptions¦CenterHorizontal=True¦CenterVertical=True¦PrintScale=1.00¦XCorrection=1.00¦YCorrection=1.00¦PrintKind=0¦BorderSize=5000000¦LeftOffset=0¦BottomOffset=0¦Orientation=2¦PaperLength=1000¦PaperWidth=1000¦Scale=100¦PaperSource=15¦PrintQuality=600¦MediaType=1¦DitherType=10¦PaperKind=Letter¦PrintScaleMode=1
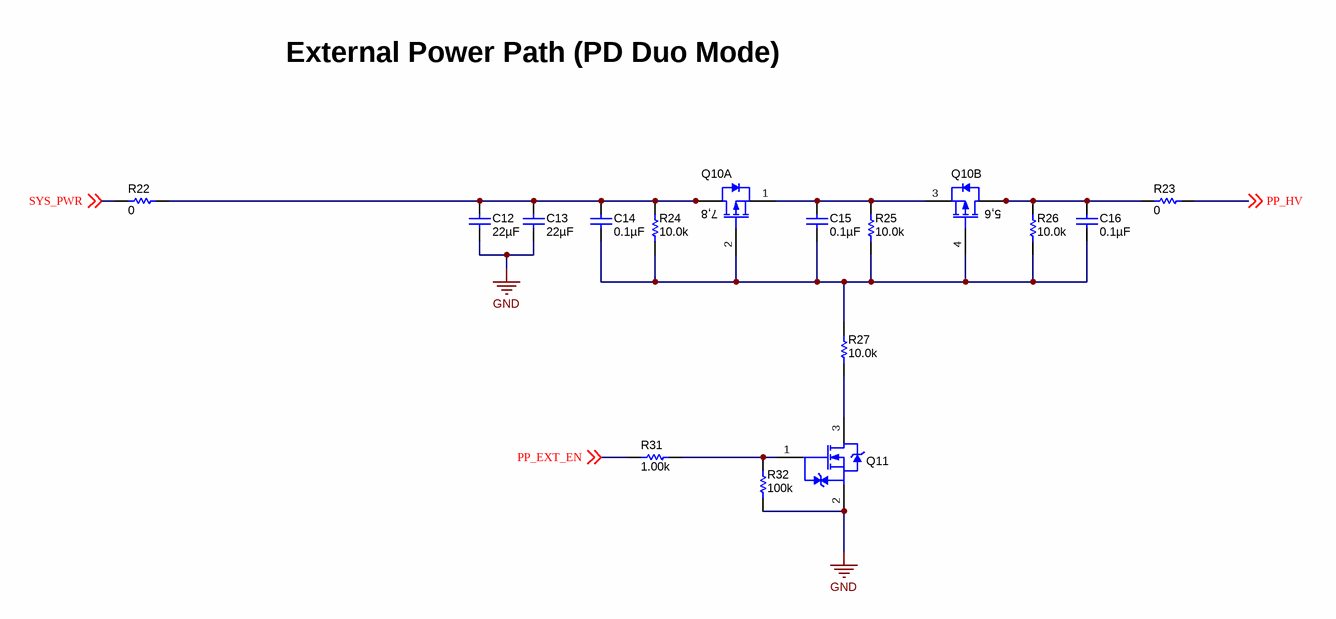
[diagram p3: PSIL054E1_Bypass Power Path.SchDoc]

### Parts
C12  ValueDisplayed: 22µF  [0805_HV]  (hidden comment: C2012X5R1V226M125AC)
C13  ValueDisplayed: 22µF  [0805_HV]  (hidden comment: C2012X5R1V226M125AC)
C14  ValueDisplayed: 0.1µF  [0402]  (hidden comment: GMK105BJ104KV-F)
C15  ValueDisplayed: 0.1µF  [0402]  (hidden comment: GRM155R71E104KE14D)
C16  ValueDisplayed: 0.1µF  [0402]  (hidden comment: GRM155R71E104KE14D)
Q10  SI7997DP-T1-GE3  [PowerPAK_SO-8 _Dual]  (value not drawn)  (parts A,B of 2)
Q11  NX3008NBKW,115  [SOT-323]  (value not drawn)
R22  ValueDisplayed: 0  [2010]  (hidden comment: CRCW20100000Z0EF)
R23  ValueDisplayed: 0  [2010]  (hidden comment: CRCW20100000Z0EF)
R24  ValueDisplayed: 10.0k  [0402]  (hidden comment: ERJ-2RKF1002X)
R25  ValueDisplayed: 10.0k  [0402]  (hidden comment: ERJ-2RKF1002X)
R26  ValueDisplayed: 10.0k  [0402]  (hidden comment: ERJ-2RKF1002X)
R27  ValueDisplayed: 10.0k  [0402]  (hidden comment: ERJ-2RKF1002X)
R31  ValueDisplayed: 1.00k  [0402]  (hidden comment: ERJ-2RKF1001X)
R32  ValueDisplayed: 100k  [0402]  (hidden comment: CRCW0402100KFKED)

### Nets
GND: C12.2 C13.2 Q11.2(S) R32.1
PP_EXT_EN: R31.2 ; off-sheet PP_EXT_EN
PP_HV: R23.2 ; off-sheet PP_HV
SYS_PWR: R22.1 ; off-sheet SYS_PWR
NetC12_1: C12.1 C13.1 C14.1 Q10.7(D) Q10.8(D) R22.2 R24.2
NetC14_2: C14.2 C15.2 C16.2 Q10.2(G) Q10.4(G) R24.1 R25.1 R26.1 R27.2
NetC15_1: C15.1 Q10.1(S) Q10.3(S) R25.2
NetC16_1: C16.1 Q10.5(D) Q10.6(D) R23.1 R26.2
NetQ11_1: Q11.1(G) R31.1 R32.2
NetQ11_3: Q11.3(D) R27.1

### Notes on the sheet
- External Power Path (PD Duo Mode)

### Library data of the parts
C12 C13 = C2012X5R1V226M125AC: as C3 on sheet PSIL054E1_Variable DCDC
C14 = GMK105BJ104KV-F: CAP, CERM, 0.1 µF, 35 V,+/- 10%, X5R, 0402; Manufacturer: Taiyo Yuden; Polarized: N; CompType: Capacitor; Value: 0.1uF; U/M: EA; Cap_F: 0.0000001; Tolerance_%: 10; VDC_V: 35; Value2: 35V; TaMin_C: -55; TaMax_C: 85; SizeArea_mm2: 0.5; SizeAreaWB_mm2: 3; SizeX_mm: 1; SizeZ_mm: 0.6; AEC Category: Q200; Green_Lifecycle: Active; Green_REACh: Passed
C15 C16 = GRM155R71E104KE14D: CAP, CERM, 0.1 µF, 25 V,+/- 10%, X7R, 0402; Manufacturer: MuRata; Polarized: N; CompType: Capacitor; Value: 0.1uF; U/M: EA; Cap_F: 0.0000001; Tolerance_%: 10; VDC_V: 25; Value2: 25V; TaMin_C: -55; TaMax_C: 125; SizeArea_mm2: 0.5; SizeAreaWB_mm2: 3; SizeX_mm: 1; SizeZ_mm: 0.6; AEC Category: Q200; Green_Lifecycle: Active; Green_REACh: Passed
Q10 = CMP-0000129-2: MOSFET, 2-CH, P-CH, -30 V, -60 A, 610x604x515mm; Alternate Manufacturer: None; Manufacturer: Vishay-Siliconix; SizeZ_mm: 1.12; ChType: P; Value2: 51 nC; Value1: 0.007; VdsMax_V: -30V; SizeX_mm: 6.15; SizeY_mm: 5.15; Vgs_V: -20V; AEC Qualified: N; Value: -30V; Rdson45_ohm: 7.8m; SizeArea_mm2: 31.6725; AEC Category: Q101; IdsMax_A: -60A; SizeAreaWB_mm2: 58.2725; U/M: EA; QgTyp_nC: 51
Q11 = NX3008NBKW,115: MOSFET, N-CH, 30 V, 0.35 A, AEC-Q101, SOT-323; Manufacturer: NXP Semiconductor; Alternate Manufacturer: None; SymbolCreator: a0411947; U/M: EA; ChType: N; Value: 30V; VdsMax_V: 30; Value1: 1.4 ohm; Rdson45_ohm: 1.4; Value2: 0.52 nC; QgTyp_nC: 0.52; Vgs_V: 8; IdsMax_A: 0.35; SizeAreaWB_mm2: 10.24; SizeArea_mm2: 4.84; SizeX_mm: 2.2; SizeZ_mm: 1.1; AEC Category: Q101; AEC Qualified: Y
R22 R23 = CMP-0016044-3: RES, 0, 5%, 0.75 W, AEC-Q200 Grade 0, 2010; Manufacturer: Vishay-Dale; Power_W: 750mW; TempCo: ppm/C; Value_Code: 0000; Value: 0; EIA_Code: E24; SizeX_mm: 5; SizeY_mm: 2.5; SizeZ_mm: 1.66; Value2: 0.75W; SizeArea_mm2: 12.5; CompType: Resistor; AEC Qualified: Y; AEC Category: Q200
R24-R27 = ERJ-2RKF1002X: as R8 on sheet PSIL054E1_Variable DCDC
R31 = ERJ-2RKF1001X: RES, 1.00 k, 1%, 0.1 W, 0402; Manufacturer: Panasonic; CompType: Resistor; Value: 1.00k; Res_ohm: 1000; Value_Code: 1k00; Tolerance_%: 1; Power_W: 0.1; Value2: 0.1W; VDC_V: 50; TempCo: 100 ppm/C; SizeArea_mm2: 0.5; SizeZ_mm: 0.6; EIA_Code: E96; U/M: EA; AEC Category: Q200; Green_Lifecycle: Active; Green_REACh: Passed
R32 = CRCW0402100KFKED: as R2 on sheet PSIL054E1_Variable DCDC

## Sheet PSIL054E1_Source Type-C Connector.SchDoc
size 431 x 279 mm; Date: Not shown in title block; ApprovedBy: Not shown in title block; CheckedBy: Not shown in title block; Author: Not shown in title block; CompanyName: Not shown in title block; Engineer: Not shown in title block; Organization: Not shown in title block; Address1: Not shown in title block; Address2: Not shown in title block; Address3: Not shown in title block; Address4: Not shown in title block; DocumentNumber: 1; Revision: Use project parameter SCH_Rev; SheetNumber: 5; SheetTotal: 9; PageSetup: Record=PageOptions¦CenterHorizontal=True¦CenterVertical=True¦PrintScale=1.00¦XCorrection=1.00¦YCorrection=1.00¦PrintKind=0¦BorderSize=5000000¦LeftOffset=0¦BottomOffset=0¦Orientation=2¦PaperLength=1000¦PaperWidth=1000¦Scale=100¦PaperSource=15¦PrintQuality=600¦MediaType=1¦DitherType=10¦PaperKind=Letter¦PrintScaleMode=1
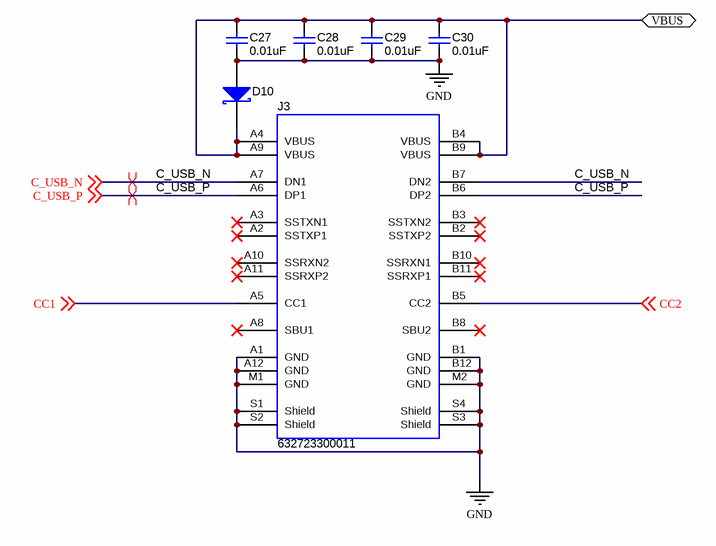
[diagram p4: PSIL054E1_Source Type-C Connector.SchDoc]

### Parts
C27  ValueDisplayed: 0.01uF  [0402]  (hidden comment: GRM155R71H103KA88D)
C28  ValueDisplayed: 0.01uF  [0402]  (hidden comment: GRM155R71H103KA88D)
C29  ValueDisplayed: 0.01uF  [0402]  (hidden comment: GRM155R71H103KA88D)
C30  ValueDisplayed: 0.01uF  [0402]  (hidden comment: GRM155R71H103KA88D)
D10  NSR20F30NXT5G  [DSN2_0603]  (value not drawn)
J3  632723300011  [Wurth_632_723_300_011]

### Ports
VBUS

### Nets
GND: C27.2 C28.2 C29.2 C30.2 D10.2(A) J3.A1(GND) J3.A12(GND) J3.B1(GND) J3.B12(GND) J3.M1(GND) J3.M2(GND) J3.S1(Shield) J3.S2(Shield) J3.S3(Shield) J3.S4(Shield)
C_USB_N: J3.A7(DN1) J3.B7(DN2) ; off-sheet C_USB_N
C_USB_P: J3.A6(DP1) J3.B6(DP2) ; off-sheet C_USB_P
CC1: J3.A5(CC1) ; off-sheet CC1
CC2: J3.B5(CC2) ; off-sheet CC2
VBUS: C27.1 C28.1 C29.1 C30.1 D10.1(K) J3.A4(VBUS) J3.A9(VBUS) J3.B4(VBUS) J3.B9(VBUS) ; port VBUS

Not connected (* = marked no-connect by the designer): J3 A2(SSTXP1)* A3(SSTXN1)* A8(SBU1)* A10(SSRXN2)* A11(SSRXP2)* B2(SSTXP2)* B3(SSTXN2)* B8(SBU2)* B10(SSRXN1)* B11(SSRXP1)*

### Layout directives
differential pair: C_USB_N, C_USB_P

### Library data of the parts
C27-C30 = CMP-0006674-2: CAP, CERM, 0.01 uF, 50 V, +/- 10%, X7R, 0402; Manufacturer: MuRata; TaMin_C: -55°C; Polarized: N; SizeAreaWB_mm2: 3; Value1: Unknown; U/M: EA; Value: 0.01uF; TaMax_C: 125°C; SizeZ_mm: 0.6; SizeX_mm: 1; SizeY_mm: 0.5; Value2: 50V; CompType: Capacitor; Cap_F: 10nF; AEC Category: Q200
D10 = CMP-0028829-1: Diode, Schottky, 30 V, 2 A, 2-XFDFN; Manufacturer: ON Semiconductor; Io_A: 2A; Green_Lifecycle: Not Set; SizeAreaWB_mm2: 4.68; Vr_V: 30V; Green_REACh: Incomplete; TJmax_C: 150°C; U/M: EA; Value: 30V; SizeZ_mm: 0.31; SizeX_mm: 1.6; SizeY_mm: 0.8; Vf_V: 4.8dV; Value2: 0.48V; SizeArea_mm2: 1.28; AEC Qualified: N; AEC Category: Q101
J3 = CMP-0080891-1: Connector, Receptacle, USB Type C, R/A; Manufacturer: Wurth Elektronik; Current_A: 3A; Gender: Female; Voltage_V: 5V; ContactFinish: Gold; Cert_UL: Y

## Sheet PSIL054E1_Sink PD Controller.SchDoc
size 431 x 279 mm; Date: Not shown in title block; ApprovedBy: Not shown in title block; CheckedBy: Not shown in title block; Author: Not shown in title block; CompanyName: Not shown in title block; Engineer: Not shown in title block; Organization: Not shown in title block; Address1: Not shown in title block; Address2: Not shown in title block; Address3: Not shown in title block; Address4: Not shown in title block; DocumentNumber: 1; Revision: Use project parameter SCH_Rev; SheetNumber: 6; SheetTotal: 9; PageSetup: Record=PageOptions¦CenterHorizontal=True¦CenterVertical=True¦PrintScale=1.00¦XCorrection=1.00¦YCorrection=1.00¦PrintKind=0¦BorderSize=5000000¦LeftOffset=0¦BottomOffset=0¦Orientation=2¦PaperLength=1000¦PaperWidth=1000¦Scale=100¦PaperSource=15¦PrintQuality=600¦MediaType=1¦DitherType=10¦PaperKind=Letter¦PrintScaleMode=1
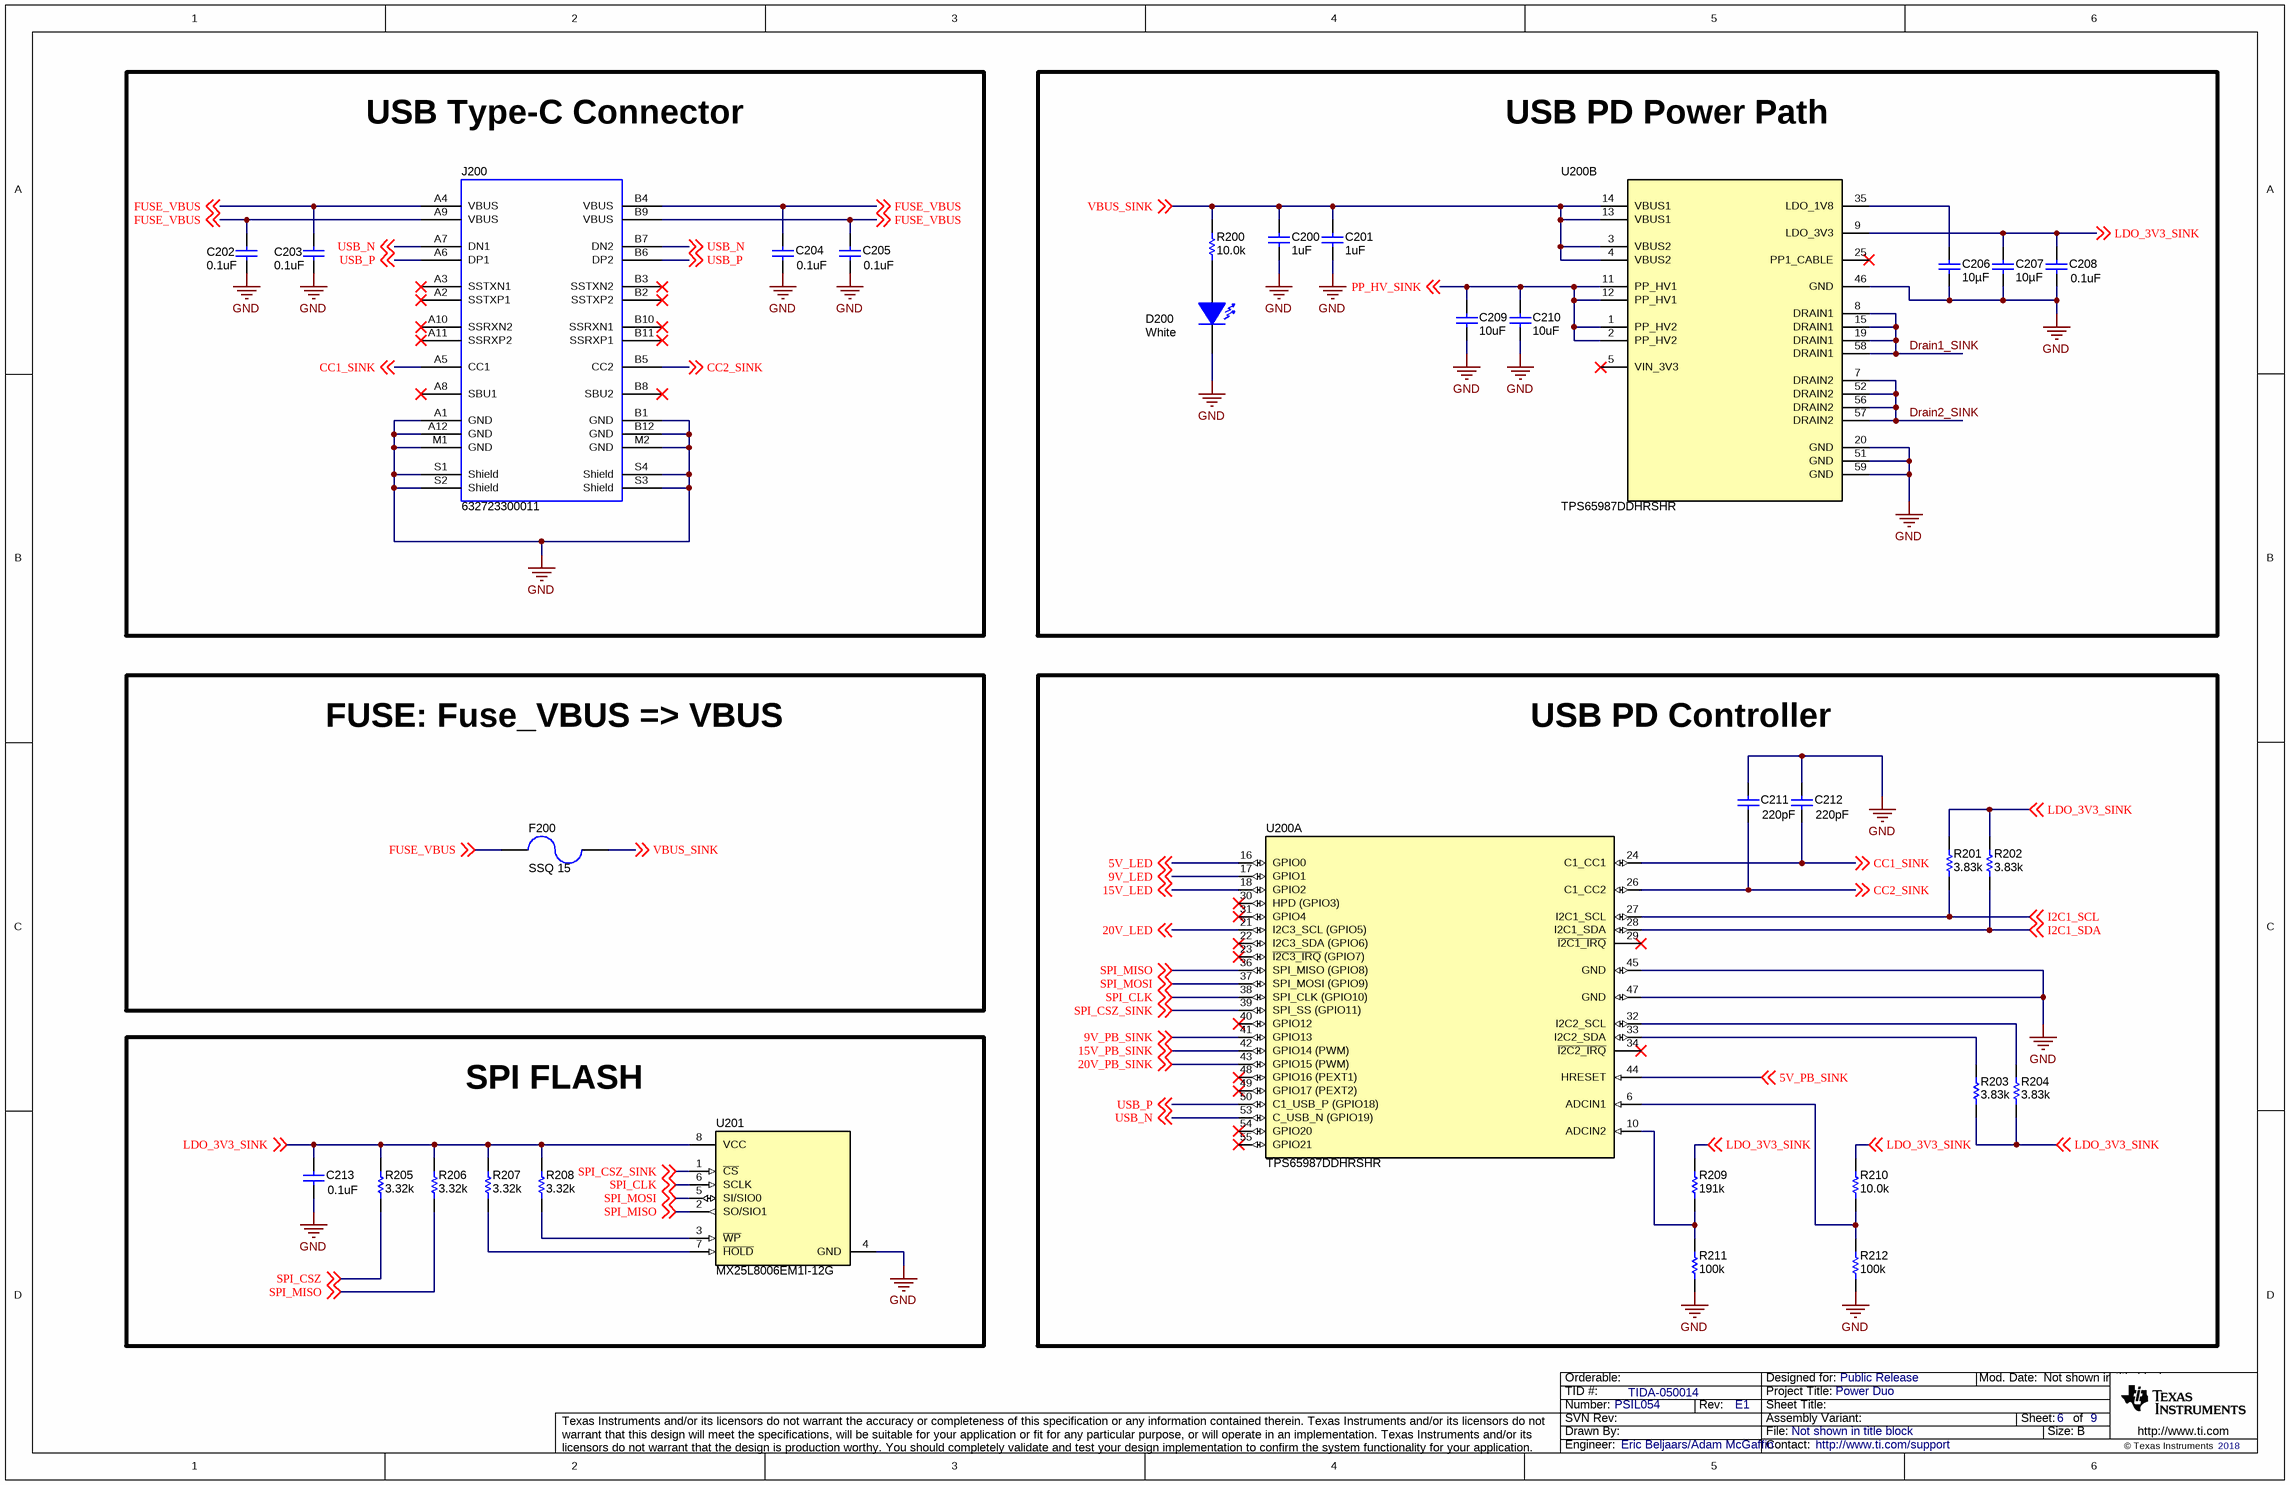
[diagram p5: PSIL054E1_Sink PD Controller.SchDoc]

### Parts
C200  ValueDisplayed: 1uF  [0603]  (hidden comment: GRM188R61H105KAALD)
C201  ValueDisplayed: 1uF  [0603]  (hidden comment: GRM188R61H105KAALD)
C202  ValueDisplayed: 0.1uF  [0402]  (hidden comment: GCM155R71H104KE02D)
C203  ValueDisplayed: 0.1uF  [0402]  (hidden comment: GCM155R71H104KE02D)
C204  ValueDisplayed: 0.1uF  [0402]  (hidden comment: GCM155R71H104KE02D)
C205  ValueDisplayed: 0.1uF  [0402]  (hidden comment: GCM155R71H104KE02D)
C206  ValueDisplayed: 10µF  [0402_070]  (hidden comment: GRM155R61A106ME44)
C207  ValueDisplayed: 10µF  [0402_070]  (hidden comment: GRM155R61A106ME44)
C208  ValueDisplayed: 0.1uF  [0201_033]  (hidden comment: GRM033R61E104KE14J)
C209  ValueDisplayed: 10uF  [0805_HV]  (hidden comment: C2012X5R1V106K085AC)
C210  ValueDisplayed: 10uF  [0805_HV]  (hidden comment: C2012X5R1V106K085AC)
C211  ValueDisplayed: 220pF  [0201]  (hidden comment: GRM033R71E221KA01D)
C212  ValueDisplayed: 220pF  [0201]  (hidden comment: GRM033R71E221KA01D)
C213  ValueDisplayed: 0.1uF  [0201_033]  (hidden comment: GRM033R61E104KE14J)
D200  value White  [LW QH8G_White]  (hidden comment: LW QH8G-Q2S2-3K5L-1)
F200  SSQ 15  [FUSE_SSQ]
J200  632723300011  [Wurth_632_723_300_011]
R200  ValueDisplayed: 10.0k  [TNPW0603]  (hidden comment: TNPW060310K0BEEA)
R201  ValueDisplayed: 3.83k  [0201]  (hidden comment: CRCW02013K83FKED)
R202  ValueDisplayed: 3.83k  [0201]  (hidden comment: CRCW02013K83FKED)
R203  ValueDisplayed: 3.83k  [0201]  (hidden comment: CRCW02013K83FKED)
R204  ValueDisplayed: 3.83k  [0201]  (hidden comment: CRCW02013K83FKED)
R205  ValueDisplayed: 3.32k  [0201]  (hidden comment: RC0201FR-073K32L)
R206  ValueDisplayed: 3.32k  [0201]  (hidden comment: RC0201FR-073K32L)
R207  ValueDisplayed: 3.32k  [0201]  (hidden comment: RC0201FR-073K32L)
R208  ValueDisplayed: 3.32k  [0201]  (hidden comment: RC0201FR-073K32L)
R209  ValueDisplayed: 191k  [0201]  (hidden comment: RC0201FR-07191KL)
R210  ValueDisplayed: 10.0k  [0201]  (hidden comment: MCR006YRTF1002)
R211  ValueDisplayed: 100k  [0201]  (hidden comment: RC0201FR-7D100KL)
R212  ValueDisplayed: 100k  [0201]  (hidden comment: RC0201FR-7D100KL)
U200  TPS65987DDHRSHR  [RSH0056E]  (parts A,B of 2)
U201  MX25L8006EM1I-12G  [SOP-8_150MIL]

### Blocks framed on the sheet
USB Type-C Connector: C202-C205 J200
USB PD Power Path: C200 C201 C206-C210 D200 R200 U200
FUSE: Fuse_VBUS => VBUS: F200
USB PD Controller: C211 C212 R201-R204 R209-R212 U200
SPI FLASH: C213 R205-R208 U201

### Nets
GND: C200.2 C201.2 C202.2 C203.2 C204.2 C205.2 C206.2 C207.2 C208.2 C209.2 C210.2 C211.1 C212.1 C213.2 D200.2(K) J200.A1(GND) J200.A12(GND) J200.B1(GND) J200.B12(GND) J200.M1(GND) J200.M2(GND) J200.S1(Shield) J200.S2(Shield) J200.S3(Shield) J200.S4(Shield) R211.1 R212.1 U200.20(GND) U200.45(GND) U200.46(GND) U200.47(GND) U200.51(GND) U200.59(GND) U201.4(GND)
5V_LED: U200.16(GPIO0) ; off-sheet 5V_LED
5V_PB_SINK: U200.44(HRESET) ; off-sheet 5V_PB_SINK
9V_LED: U200.17(GPIO1) ; off-sheet 9V_LED
9V_PB_SINK: U200.41(GPIO13) ; off-sheet 9V_PB_SINK
15V_LED: U200.18(GPIO2) ; off-sheet 15V_LED
15V_PB_SINK: U200.42(GPIO14_(PWM)) ; off-sheet 15V_PB_SINK
20V_LED: U200.21(I2C3_SCL_(GPIO5)) ; off-sheet 20V_LED
20V_PB_SINK: U200.43(GPIO15_(PWM)) ; off-sheet 20V_PB_SINK
CC1_SINK: C212.2 J200.A5(CC1) U200.24(C1_CC1) ; off-sheet CC1_SINK
CC2_SINK: C211.2 J200.B5(CC2) U200.26(C1_CC2) ; off-sheet CC2_SINK
Drain1_SINK: U200.8(DRAIN1) U200.15(DRAIN1) U200.19(DRAIN1) U200.58(DRAIN1)
Drain2_SINK: U200.7(DRAIN2) U200.52(DRAIN2) U200.56(DRAIN2) U200.57(DRAIN2)
FUSE_VBUS: C202.1 C203.1 C204.1 C205.1 F200.2 J200.A4(VBUS) J200.A9(VBUS) J200.B4(VBUS) J200.B9(VBUS) ; off-sheet FUSE_VBUS
I2C1_SCL: R201.1 U200.27(I2C1_SCL) ; off-sheet I2C1_SCL
I2C1_SDA: R202.1 U200.28(I2C1_SDA) ; off-sheet I2C1_SDA
LDO_3V3_SINK: C207.1 C208.1 C213.1 R201.2 R202.2 R203.1 R204.1 R205.2 R206.2 R207.2 R208.2 R209.2 R210.2 U200.9(LDO_3V3) U201.8(VCC) ; off-sheet LDO_3V3_SINK
PP_HV_SINK: C209.1 C210.1 U200.1(PP_HV2) U200.2(PP_HV2) U200.11(PP_HV1) U200.12(PP_HV1) ; off-sheet PP_HV_SINK
SPI_CLK: U200.38(SPI_CLK_(GPIO10)) U201.6(SCLK) ; off-sheet SPI_CLK
SPI_CSZ: R205.1 ; off-sheet SPI_CSZ
SPI_CSZ_SINK: U200.39(SPI_SS_(GPIO11)) U201.1(~{CS}) ; off-sheet SPI_CSZ_SINK
SPI_MISO: R206.1 U200.36(SPI_MISO_(GPIO8)) U201.2(SO/SIO1) ; off-sheet SPI_MISO
SPI_MOSI: U200.37(SPI_MOSI_(GPIO9)) U201.5(SI/SIO0) ; off-sheet SPI_MOSI
USB_N: J200.A7(DN1) J200.B7(DN2) U200.53(C_USB_N_(GPIO19)) ; off-sheet USB_N
USB_P: J200.A6(DP1) J200.B6(DP2) U200.50(C1_USB_P_(GPIO18)) ; off-sheet USB_P
VBUS_SINK: C200.1 C201.1 F200.1 R200.2 U200.3(VBUS2) U200.4(VBUS2) U200.13(VBUS1) U200.14(VBUS1) ; off-sheet VBUS_SINK
NetC206_1: C206.1 U200.35(LDO_1V8)
NetD200_1: D200.1(A) R200.1
NetR203_2: R203.2 U200.33(I2C2_SDA)
NetR204_2: R204.2 U200.32(I2C2_SCL)
NetR207_1: R207.1 U201.7(~{HOLD})
NetR208_1: R208.1 U201.3(~{WP})
NetR209_1: R209.1 R211.2 U200.10(ADCIN2)
NetR210_1: R210.1 R212.2 U200.6(ADCIN1)

Not connected (* = marked no-connect by the designer): J200 A2(SSTXP1)* A3(SSTXN1)* A8(SBU1)* A10(SSRXN2)* A11(SSRXP2)* B2(SSTXP2)* B3(SSTXN2)* B8(SBU2)* B10(SSRXN1)* B11(SSRXP1)*; U200 5(VIN_3V3)* 22(I2C3_SDA_(GPIO6))* 23(~{I2C3_IRQ}_(GPIO7))* 25(PP1_CABLE)* 29(~{I2C1_IRQ})* 30(HPD_(GPIO3))* 31(GPIO4)* 34(~{I2C2_IRQ})* 40(GPIO12)* 48(GPIO16_(PEXT1))* 49(GPIO17_(PEXT2))* 54(GPIO20)* 55(GPIO21)*

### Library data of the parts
C200 C201 = CMP-0007350-5: CAP, CERM, 1 uF, 50 V, +/- 10%, X5R, 0603; Manufacturer: MuRata; TaMin_C: -55°C; Polarized: N; SizeAreaWB_mm2: 4.68; Value1: Unknown; U/M: EA; Value: 1uF; TaMax_C: 85°C; SizeZ_mm: 1; SizeX_mm: 1.6; SizeY_mm: 0.8; Value2: 50V; SizeArea_mm2: 1.28; CompType: Capacitor; Cap_F: 1µF; AEC Category: Q200
C202-C205 = CMP-0006356-2: CAP, CERM, 0.1 uF, 50 V, +/- 10%, X7R, AEC-Q200 Grade 1, 0402; Manufacturer: MuRata; TaMin_C: -55°C; Polarized: N; SizeAreaWB_mm2: 3; Value1: Unknown; U/M: EA; Value: 0.1uF; TaMax_C: 125°C; SizeZ_mm: 0.6; SizeX_mm: 1; SizeY_mm: 0.5; Value2: 50V; CompType: Capacitor; AEC Qualified: Y; Cap_F: 100nF; AEC Category: Q200
C206 C207 = CMP-0074692-1: CAP, CERM, 10 µF, 10 V,+/- 20%, X5R, 0402; Manufacturer: MuRata; TaMin_C: -55°C; Polarized: N; Green_Lifecycle: Not Set; SizeAreaWB_mm2: 3.0; Green_REACh: Incomplete; U/M: EA; Value: 10uF; TaMax_C: 85°C; SizeZ_mm: 0.7; SizeX_mm: 1.0; SizeY_mm: 0.5; Cap_Case: 0402; Value2: 10V; CompType: Capacitor; AEC Category: Q200
C208 C213 = CMP-0009719-2: CAP, CERM, 0.1 uF, 25 V, +/- 10%, X5R, 0201; Manufacturer: MuRata; TaMin_C: -55°C; Polarized: N; SizeAreaWB_mm2: 2.08; Value1: Unknown; U/M: EA; Value: 0.1uF; TaMax_C: 85°C; SizeZ_mm: 0.33; SizeX_mm: 0.6; SizeY_mm: 0.3; Cap_Case: 0201; Value2: 25V; SizeArea_mm2: 0.18; CompType: Capacitor; Cap_F: 100nF; AEC Category: Q200
C209 C210 = CMP-0007842-2: CAP, CERM, 10 uF, 35 V, +/- 10%, X5R, 0805; Manufacturer: TDK; TaMin_C: -55°C; ESR_ohm: 2.818m; Polarized: N; SizeAreaWB_mm2: 6.75; Value1: 0.002818 ohm; U/M: EA; Value: 10uF; TaMax_C: 85°C; SizeZ_mm: 1.45; SizeX_mm: 2; SizeY_mm: 1.25; Cap_Case: 0805; Value2: 35V; SizeArea_mm2: 2.5; CompType: Capacitor; Cap_F: 10µF; IRMS_A: 3.88676A; AEC Category: Q200
C211 C212 = CMP-0009770-1: CAP, CERM, 220 pF, 25 V, +/- 10%, X7R, 0201; Manufacturer: MuRata; TaMin_C: -55°C; Polarized: N; SizeAreaWB_mm2: 2.08; Value1: Unknown; U/M: EA; Value: 220pF; TaMax_C: 125°C; SizeZ_mm: 0.26; SizeX_mm: 0.6; SizeY_mm: 0.3; Value2: 25V; SizeArea_mm2: 0.18; CompType: Capacitor; AEC Category: Q200
D200 = LW QH8G-Q2S2-3K5L-1: as D5 on sheet PSIL054E1_Variable DCDC
F200 = CMP-0003604-2: Fuse, 15 A, SMD; Manufacturer: Bel Fuse; Irating_A: 15A; Rtyp_Ohm: 4m
J200 = CMP-0080891-1: as J3 on sheet PSIL054E1_Source Type-C Connector
R200 = CMP-0025686-1: RES, 10.0 k, 0.1%, 0.1 W, AEC-Q200 Grade 1, 0603; Manufacturer: Vishay-Dale; Power_W: 100mW; TempCo: 25 ppm/C; Value_Code: 10k0; U/M: EA; Value: 10.0k; EIA_Code: E192; Res_ohm: 10k; SizeX_mm: 1.6; SizeY_mm: 0.85; SizeZ_mm: 0.55; Value2: 0.1W; SizeArea_mm2: 1.36; CompType: Resistor; AEC Qualified: Y; VDC_V: 75V; AEC Grade: 1; AEC Category: Q200
R201-R204 = CMP-0027277-3: RES, 3.83 k, 1%, 0.05 W, 0201; Manufacturer: Vishay-Dale; Power_W: 50mW; TempCo: 100 ppm/C; Value_Code: 3k83; Value: 3.83k; EIA_Code: E96; SizeX_mm: 0.6; SizeY_mm: 0.3; SizeZ_mm: 0.26; Value2: 0.05W; SizeArea_mm2: 0.18; AEC Qualified: N; VDC_V: 30V; AEC Category: Q200
R205-R208 = CMP-0027656-1: RES, 3.32 k, 1%, 0.05 W, 0201; Manufacturer: Yageo America; Power_W: 50mW; TempCo: 200 ppm/C; Value_Code: 3k32; U/M: EA; Value: 3.32k; EIA_Code: E96; SizeX_mm: 0.6; SizeY_mm: 0.3; SizeZ_mm: 0.26; Value2: 0.05W; SizeArea_mm2: 0.18; AEC Qualified: N; VDC_V: 25V; AEC Category: Q200
R209 = CMP-0027414-1: RES, 191 k, 1%, 0.05 W, 0201; Manufacturer: Yageo America; Power_W: 50mW; TempCo: 200 ppm/C; U/M: EA; Value: 191k; EIA_Code: E96; SizeX_mm: 0.6; SizeY_mm: 0.3; SizeZ_mm: 0.26; Value2: 0.05W; SizeArea_mm2: 0.18; AEC Qualified: N; VDC_V: 25V; AEC Category: Q200
R210 = CMP-0027291-2: RES, 10.0 k, 1%, 0.05 W, 0201; Manufacturer: Rohm; Power_W: 50mW; TempCo: 250 ppm/C; Value_Code: 10k0; U/M: EA; Value: 10.0k; EIA_Code: E96; Res_ohm: 10k; SizeX_mm: 0.6; SizeY_mm: 0.3; SizeZ_mm: 0.26; Value2: 0.05W; SizeArea_mm2: 0.18; VDC_V: 25V; AEC Category: Q200
R211 R212 = CMP-0027943-1: RES, 100 k, 1%, 0.05 W, 0201; Manufacturer: Yageo America; Power_W: 50mW; TempCo: 200 ppm/C; U/M: EA; Value: 100k; EIA_Code: E96; SizeX_mm: 0.6; SizeY_mm: 0.3; SizeZ_mm: 0.26; Value2: 0.05W; SizeArea_mm2: 0.18; AEC Qualified: N; VDC_V: 25V; AEC Category: Q200
U200 = CMP-0081032-2: as U5 on sheet PSIL054E1_Source PD Controller
U201 = CMP-0078948-1: as U6 on sheet PSIL054E1_Source PD Controller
